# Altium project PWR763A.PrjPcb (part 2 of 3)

## Sheet PWR763A_3.SchDoc: PWR763A
size 431 x 279 mm; Date: Not shown in title block; ApprovedBy: Not shown in title block; CheckedBy: Not shown in title block; Author: Not shown in title block; CompanyName: Not shown in title block; Engineer: Not shown in title block; Organization: Not shown in title block; Address1: Not shown in title block; Address2: Not shown in title block; Address3: Not shown in title block; Address4: Not shown in title block; DocumentNumber: 1; Revision: Use project parameter SCH_Rev; SheetNumber: 3; SheetTotal: 6; PageSetup: Record=PageOptions¦CenterHorizontal=True¦CenterVertical=True¦PrintScale=1.00¦XCorrection=1.00¦YCorrection=1.00¦PrintKind=0¦BorderSize=5000000¦LeftOffset=0¦BottomOffset=0¦Orientation=2¦PaperLength=1000¦PaperWidth=1000¦Scale=100¦PaperSource=15¦PrintQuality=600¦MediaType=1¦DitherType=10¦PaperKind=Letter¦PrintScaleMode=1
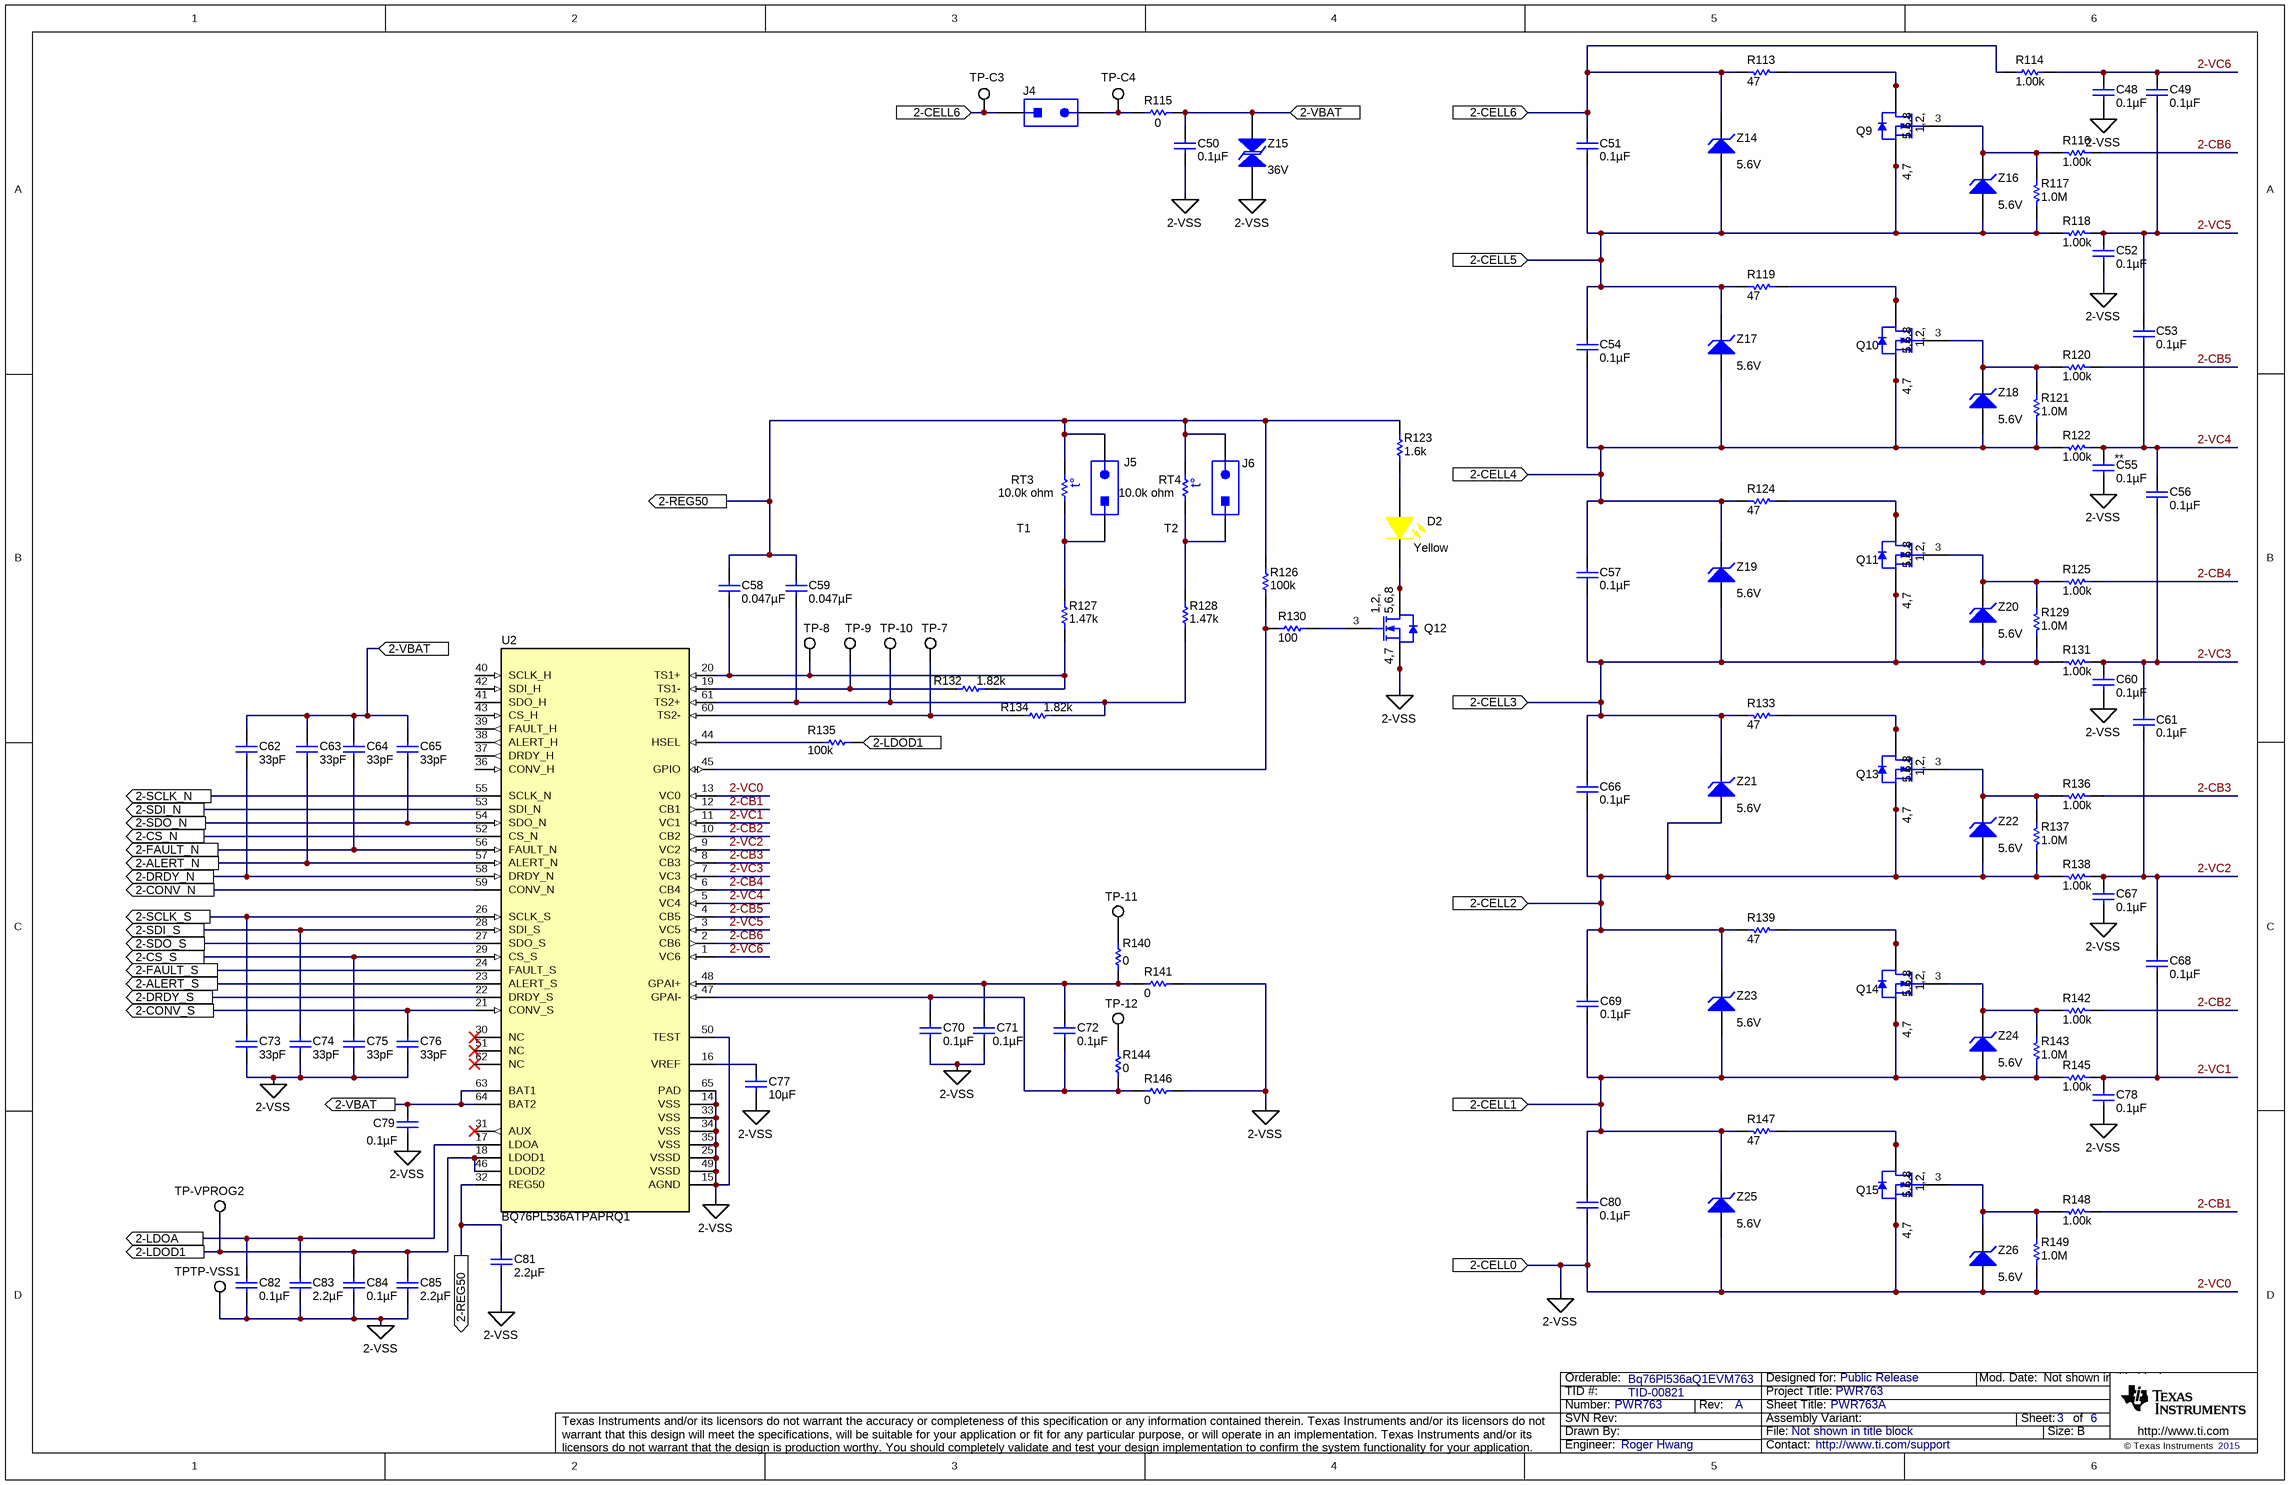
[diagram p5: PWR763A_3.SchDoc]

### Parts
C48  ValueDisplayed: 0.1µF  [0603]  (hidden comment: 06035C104KAT2A)
C49  ValueDisplayed: 0.1µF  [0603]  (hidden comment: GRM188R72A104KA35D)
C50  ValueDisplayed: 0.1µF  [0603]  (hidden comment: GRM188R72A104KA35D)
C51  ValueDisplayed: 0.1µF  [0603]  (hidden comment: 06035C104KAT2A)
C52  ValueDisplayed: 0.1µF  [0603]  (hidden comment: 06035C104KAT2A)
C53  ValueDisplayed: 0.1µF  [0603]  (hidden comment: GRM188R72A104KA35D)
C54  ValueDisplayed: 0.1µF  [0603]  (hidden comment: 06035C104KAT2A)
C55  ValueDisplayed: 0.1µF  [0603]  (hidden comment: 06035C104KAT2A)
C56  ValueDisplayed: 0.1µF  [0603]  (hidden comment: GRM188R72A104KA35D)
C57  ValueDisplayed: 0.1µF  [0603]  (hidden comment: 06035C104KAT2A)
C58  ValueDisplayed: 0.047µF  [0603]  (hidden comment: GRM188R71C473KA01D)
C59  ValueDisplayed: 0.047µF  [0603]  (hidden comment: GRM188R71C473KA01D)
C60  ValueDisplayed: 0.1µF  [0603]  (hidden comment: 06035C104KAT2A)
C61  ValueDisplayed: 0.1µF  [0603]  (hidden comment: GRM188R72A104KA35D)
C62  ValueDisplayed: 33pF  [0603]  (hidden comment: GRM1885C1H330JA01D)
C63  ValueDisplayed: 33pF  [0603]  (hidden comment: GRM1885C1H330JA01D)
C64  ValueDisplayed: 33pF  [0603]  (hidden comment: GRM1885C1H330JA01D)
C65  ValueDisplayed: 33pF  [0603]  (hidden comment: GRM1885C1H330JA01D)
C66  ValueDisplayed: 0.1µF  [0603]  (hidden comment: 06035C104KAT2A)
C67  ValueDisplayed: 0.1µF  [0603]  (hidden comment: 06035C104KAT2A)
C68  ValueDisplayed: 0.1µF  [0603]  (hidden comment: GRM188R72A104KA35D)
C69  ValueDisplayed: 0.1µF  [0603]  (hidden comment: GRM188R72A104KA35D)
C70  ValueDisplayed: 0.1µF  [0603]  (hidden comment: C0603C104K4RACTU)
C71  ValueDisplayed: 0.1µF  [0603]  (hidden comment: C0603C104K4RACTU)
C72  ValueDisplayed: 0.1µF  [0603]  (hidden comment: C0603C104K4RACTU)
C73  ValueDisplayed: 33pF  [0603]  (hidden comment: GRM1885C1H330JA01D)
C74  ValueDisplayed: 33pF  [0603]  (hidden comment: GRM1885C1H330JA01D)
C75  ValueDisplayed: 33pF  [0603]  (hidden comment: GRM1885C1H330JA01D)
C76  ValueDisplayed: 33pF  [0603]  (hidden comment: GRM1885C1H330JA01D)
C77  ValueDisplayed: 10µF  [0805_145]  (hidden comment: C2012X7R1A106M125AC)
C78  ValueDisplayed: 0.1µF  [0603]  (hidden comment: 06035C104KAT2A)
C79  ValueDisplayed: 0.1µF  [0603]  (hidden comment: 06035C104KAT2A)
C80  ValueDisplayed: 0.1µF  [0603]  (hidden comment: 06035C104KAT2A)
C81  ValueDisplayed: 2.2µF  [0805_HV]  (hidden comment: GRM21BR71A225KA01L)
C82  ValueDisplayed: 0.1µF  [0603]  (hidden comment: 06035C104KAT2A)
C83  ValueDisplayed: 2.2µF  [0805_HV]  (hidden comment: GRM21BR71A225KA01L)
C84  ValueDisplayed: 0.1µF  [0603]  (hidden comment: 06035C104KAT2A)
C85  ValueDisplayed: 2.2µF  [0805_HV]  (hidden comment: GRM21BR71A225KA01L)
D2  value Yellow  [APT1608_Yellow]  (hidden comment: APT1608SYCK)
J4  PEC02SAAN  [CONN_PEC02SAAN]  (value not drawn)
J5  PEC02SAAN  [CONN_PEC02SAAN]  (value not drawn)
J6  PEC02SAAN  [CONN_PEC02SAAN]  (value not drawn)
Q9  CSD16301Q2  [TRANS_NexFET_Q2]  (value not drawn)
Q10  CSD16301Q2  [TRANS_NexFET_Q2]  (value not drawn)
Q11  CSD16301Q2  [TRANS_NexFET_Q2]  (value not drawn)
Q12  CSD16301Q2  [TRANS_NexFET_Q2]  (value not drawn)
Q13  CSD16301Q2  [TRANS_NexFET_Q2]  (value not drawn)
Q14  CSD16301Q2  [TRANS_NexFET_Q2]  (value not drawn)
Q15  CSD16301Q2  [TRANS_NexFET_Q2]  (value not drawn)
R113  ValueDisplayed: 47  [2512]  (hidden comment: CRCW251247R0JNEG)
R114  ValueDisplayed: 1.00k  [0603]  (hidden comment: RG1608P-102-B-T5)
R115  ValueDisplayed: 0  [0805_HV]  (hidden comment: CRCW08050000Z0EA)
R116  ValueDisplayed: 1.00k  [0603]  (hidden comment: RG1608P-102-B-T5)
R117  ValueDisplayed: 1.0M  [0603]  (hidden comment: CRCW06031M00JNEA)
R118  ValueDisplayed: 1.00k  [0603]  (hidden comment: RG1608P-102-B-T5)
R119  ValueDisplayed: 47  [2512]  (hidden comment: CRCW251247R0JNEG)
R120  ValueDisplayed: 1.00k  [0603]  (hidden comment: RG1608P-102-B-T5)
R121  ValueDisplayed: 1.0M  [0603]  (hidden comment: CRCW06031M00JNEA)
R122  ValueDisplayed: 1.00k  [0603]  (hidden comment: RG1608P-102-B-T5)
R123  ValueDisplayed: 1.6k  [0603]  (hidden comment: CRCW06031K60JNEA)
R124  ValueDisplayed: 47  [2512]  (hidden comment: CRCW251247R0JNEG)
R125  ValueDisplayed: 1.00k  [0603]  (hidden comment: RG1608P-102-B-T5)
R126  ValueDisplayed: 100k  [0603]  (hidden comment: CRCW0603100KFKEA)
R127  ValueDisplayed: 1.47k  [0603]  (hidden comment: CRCW06031K47FKEA)
R128  ValueDisplayed: 1.47k  [0603]  (hidden comment: CRCW06031K47FKEA)
R129  ValueDisplayed: 1.0M  [0603]  (hidden comment: CRCW06031M00JNEA)
R130  ValueDisplayed: 100  [0603]  (hidden comment: CRCW0603100RJNEA)
R131  ValueDisplayed: 1.00k  [0603]  (hidden comment: RG1608P-102-B-T5)
R132  ValueDisplayed: 1.82k  [0603]  (hidden comment: CRCW06031K82FKEA)
R133  ValueDisplayed: 47  [2512]  (hidden comment: CRCW251247R0JNEG)
R134  ValueDisplayed: 1.82k  [0603]  (hidden comment: CRCW06031K82FKEA)
R135  ValueDisplayed: 100k  [0603]  (hidden comment: CRCW0603100KFKEA)
R136  ValueDisplayed: 1.00k  [0603]  (hidden comment: RG1608P-102-B-T5)
R137  ValueDisplayed: 1.0M  [0603]  (hidden comment: CRCW06031M00JNEA)
R138  ValueDisplayed: 1.00k  [0603]  (hidden comment: RG1608P-102-B-T5)
R139  ValueDisplayed: 47  [2512]  (hidden comment: CRCW251247R0JNEG)
R140  ValueDisplayed: 0  [0603]  (hidden comment: CRCW06030000Z0EA)
R141  ValueDisplayed: 0  [0603]  (hidden comment: CRCW06030000Z0EA)
R142  ValueDisplayed: 1.00k  [0603]  (hidden comment: RG1608P-102-B-T5)
R143  ValueDisplayed: 1.0M  [0603]  (hidden comment: CRCW06031M00JNEA)
R144  ValueDisplayed: 0  [0603]  (hidden comment: CRCW06030000Z0EA)
R145  ValueDisplayed: 1.00k  [0603]  (hidden comment: RG1608P-102-B-T5)
R146  ValueDisplayed: 0  [0603]  (hidden comment: CRCW06030000Z0EA)
R147  ValueDisplayed: 47  [2512]  (hidden comment: CRCW251247R0JNEG)
R148  ValueDisplayed: 1.00k  [0603]  (hidden comment: RG1608P-102-B-T5)
R149  ValueDisplayed: 1.0M  [0603]  (hidden comment: CRCW06031M00JNEA)
RT3  value 10.0k ohm  [0603]  (hidden comment: ERT-J1VG103FA)
RT4  value 10.0k ohm  [0603]  (hidden comment: ERT-J1VG103FA)
TP-7  5015  [Testpoint_Keystone_Miniature]  (value not drawn)
TP-8  5015  [Testpoint_Keystone_Miniature]  (value not drawn)
TP-9  5015  [Testpoint_Keystone_Miniature]  (value not drawn)
TP-10  5015  [Testpoint_Keystone_Miniature]  (value not drawn)
TP-11  5015  [Testpoint_Keystone_Miniature]  (value not drawn)
TP-12  5015  [Testpoint_Keystone_Miniature]  (value not drawn)
TP-C3  5015  [Testpoint_Keystone_Miniature]  (value not drawn)
TP-C4  5015  [Testpoint_Keystone_Miniature]  (value not drawn)
TP-VPROG2  5015  [Testpoint_Keystone_Miniature]  (value not drawn)
TPTP-VSS1  5015  [Testpoint_Keystone_Miniature]  (value not drawn)
U2  BQ76PL536ATPAPRQ1  [PAP0064F_N]
Z14  value 5.6V  [SOD-123]  (hidden comment: MMSZ5232B-7-F)
Z15  value 36V  [SMA]  (hidden comment: SMAJ36CA)
Z16  value 5.6V  [SOD-123]  (hidden comment: MMSZ5232B-7-F)
Z17  value 5.6V  [SOD-123]  (hidden comment: MMSZ5232B-7-F)
Z18  value 5.6V  [SOD-123]  (hidden comment: MMSZ5232B-7-F)
Z19  value 5.6V  [SOD-123]  (hidden comment: MMSZ5232B-7-F)
Z20  value 5.6V  [SOD-123]  (hidden comment: MMSZ5232B-7-F)
Z21  value 5.6V  [SOD-123]  (hidden comment: MMSZ5232B-7-F)
Z22  value 5.6V  [SOD-123]  (hidden comment: MMSZ5232B-7-F)
Z23  value 5.6V  [SOD-123]  (hidden comment: MMSZ5232B-7-F)
Z24  value 5.6V  [SOD-123]  (hidden comment: MMSZ5232B-7-F)
Z25  value 5.6V  [SOD-123]  (hidden comment: MMSZ5232B-7-F)
Z26  value 5.6V  [SOD-123]  (hidden comment: MMSZ5232B-7-F)

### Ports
2-ALERT_N, 2-ALERT_S, 2-CELL0, 2-CELL1, 2-CELL2, 2-CELL3, 2-CELL4, 2-CELL5, 2-CELL6, 2-CONV_N, 2-CONV_S, 2-CS_N, 2-CS_S, 2-DRDY_N, 2-DRDY_S, 2-FAULT_N, 2-FAULT_S, 2-LDOA, 2-LDOD1, 2-REG50, 2-SCLK_N, 2-SCLK_S, 2-SDI_N, 2-SDI_S, 2-SDO_N, 2-SDO_S, 2-VBAT

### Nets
2-VC0: C48.2 C50.2 C52.2 C55.2 C60.2 C67.2 C70.2 C71.2 C73.2 C74.2 C75.2 C76.2 C77.2 C78.2 C79.2 C80.2 C81.2 C82.2 C83.2 C84.2 C85.2 Q12.4(S) Q12.7(S) Q15.4(S) Q15.7(S) R141.2 R146.2 R149.1 TPTP-VSS1.1 U2.13(VC0) U2.14(VSS) U2.15(AGND) U2.25(VSSD) U2.33(VSS) U2.34(VSS) U2.35(VSS) U2.49(VSSD) U2.50(TEST) U2.65(PAD) Z15.1 Z25.2(A) Z26.2(A) ; port 2-CELL0  [also labelled 2-VSS]
2-ALERT_N: C63.2 U2.57(ALERT_N) ; port 2-ALERT_N
2-ALERT_S: U2.23(ALERT_S) ; port 2-ALERT_S
2-CB1: R148.1 U2.12(CB1)
2-CB2: R142.1 U2.10(CB2)
2-CB3: R136.1 U2.8(CB3)
2-CB4: R125.1 U2.6(CB4)
2-CB5: R120.1 U2.4(CB5)
2-CB6: R116.1 U2.2(CB6)
2-CELL1: C69.2 C80.1 Q14.4(S) Q14.7(S) R143.1 R145.2 R147.2 Z23.2(A) Z24.2(A) Z25.1(K) ; port 2-CELL1
2-CELL2: C66.2 C69.1 Q13.4(S) Q13.7(S) R137.1 R138.2 R139.2 Z21.2(A) Z22.2(A) Z23.1(K) ; port 2-CELL2
2-CELL3: C57.2 C66.1 Q11.4(S) Q11.7(S) R129.1 R131.2 R133.2 Z19.2(A) Z20.2(A) Z21.1(K) ; port 2-CELL3
2-CELL4: C54.2 C57.1 Q10.4(S) Q10.7(S) R121.1 R122.2 R124.2 Z17.2(A) Z18.2(A) Z19.1(K) ; port 2-CELL4
2-CELL5: C51.2 C54.1 Q9.4(S) Q9.7(S) R117.1 R118.2 R119.2 Z14.2(A) Z16.2(A) Z17.1(K) ; port 2-CELL5
2-CELL6: C51.1 J4.1 R113.2 R114.2 TP-C3.1 Z14.1(K) ; port 2-CELL6
2-CONV_N: U2.59(CONV_N) ; port 2-CONV_N
2-CONV_S: C76.1 U2.21(CONV_S) ; port 2-CONV_S
2-CS_N: U2.52(CS_N) ; port 2-CS_N
2-CS_S: C75.1 U2.29(CS_S) ; port 2-CS_S
2-DRDY_N: C62.2 U2.58(DRDY_N) ; port 2-DRDY_N
2-DRDY_S: U2.22(DRDY_S) ; port 2-DRDY_S
2-FAULT_N: C64.2 U2.56(FAULT_N) ; port 2-FAULT_N
2-FAULT_S: U2.24(FAULT_S) ; port 2-FAULT_S
2-LDOA: C82.1 C83.1 U2.17(LDOA) ; port 2-LDOA
2-LDOD1: C84.1 C85.1 R135.2 TP-VPROG2.1 U2.18(LDOD1) U2.46(LDOD2) ; port 2-LDOD1
2-REG50: C58.1 C59.1 C81.1 J5.2 J6.2 R123.2 R126.2 RT3.2 RT4.2 U2.32(REG50) ; port 2-REG50
2-SCLK_N: U2.55(SCLK_N) ; port 2-SCLK_N
2-SCLK_S: C73.1 U2.26(SCLK_S) ; port 2-SCLK_S
2-SDI_N: U2.53(SDI_N) ; port 2-SDI_N
2-SDI_S: C74.1 U2.28(SDI_S) ; port 2-SDI_S
2-SDO_N: C65.2 U2.54(SDO_N) ; port 2-SDO_N
2-SDO_S: U2.27(SDO_S) ; port 2-SDO_S
2-VBAT: C50.1 C62.1 C63.1 C64.1 C65.1 C79.1 R115.2 U2.63(BAT1) U2.64(BAT2) Z15.2 ; port 2-VBAT
2-VC1: C68.2 C78.1 R145.1 U2.11(VC1)
2-VC2: C61.2 C67.1 C68.1 R138.1 U2.9(VC2)
2-VC3: C56.2 C60.1 C61.1 R131.1 U2.7(VC3)
2-VC4: C53.2 C55.1 C56.1 R122.1 U2.5(VC4)
2-VC5: C49.2 C52.1 C53.1 R118.1 U2.3(VC5)
2-VC6: C48.1 C49.1 R114.1 U2.1(VC6)
NetC58_2: C58.2 R127.1 R132.2 TP-8.1 U2.20(TS1+)
NetC59_2: C59.2 R128.1 R134.2 TP-10.1 U2.61(TS2+)
NetC70_1: C70.1 C72.2 R144.1 R146.1 U2.47(GPAI-)
NetC71_1: C71.1 C72.1 R140.1 R141.1 U2.48(GPAI+)
NetC77_1: C77.1 U2.16(VREF)
NetD2_1: D2.1(A) R123.1
NetD2_2: D2.2(K) Q12.1(D) Q12.2(D) Q12.5(D) Q12.6(D) Q12.8(D)
NetJ4_2: J4.2 R115.1 TP-C4.1
NetJ5_1: J5.1 R127.2 RT3.1
NetJ6_1: J6.1 R128.2 RT4.1
NetQ9_1: Q9.1(D) Q9.2(D) Q9.5(D) Q9.6(D) Q9.8(D) R113.1
NetQ9_3: Q9.3(G) R116.2 R117.2 Z16.1(K)
NetQ10_1: Q10.1(D) Q10.2(D) Q10.5(D) Q10.6(D) Q10.8(D) R119.1
NetQ10_3: Q10.3(G) R120.2 R121.2 Z18.1(K)
NetQ11_1: Q11.1(D) Q11.2(D) Q11.5(D) Q11.6(D) Q11.8(D) R124.1
NetQ11_3: Q11.3(G) R125.2 R129.2 Z20.1(K)
NetQ12_3: Q12.3(G) R130.2
NetQ13_1: Q13.1(D) Q13.2(D) Q13.5(D) Q13.6(D) Q13.8(D) R133.1
NetQ13_3: Q13.3(G) R136.2 R137.2 Z22.1(K)
NetQ14_1: Q14.1(D) Q14.2(D) Q14.5(D) Q14.6(D) Q14.8(D) R139.1
NetQ14_3: Q14.3(G) R142.2 R143.2 Z24.1(K)
NetQ15_1: Q15.1(D) Q15.2(D) Q15.5(D) Q15.6(D) Q15.8(D) R147.1
NetQ15_3: Q15.3(G) R148.2 R149.2 Z26.1(K)
NetR126_1: R126.1 R130.1 U2.45(GPIO)
NetR132_1: R132.1 TP-9.1 U2.19(TS1-)
NetR134_1: R134.1 TP-7.1 U2.60(TS2-)
NetR135_1: R135.1 U2.44(HSEL)
NetR140_2: R140.2 TP-11.1
NetR144_2: R144.2 TP-12.1

Not connected (* = marked no-connect by the designer): U2 30(NC)* 31(AUX)* 36(CONV_H) 37(DRDY_H) 38(ALERT_H) 39(FAULT_H) 40(SCLK_H) 41(SDO_H) 42(SDI_H) 43(CS_H) 51(NC)* 62(NC)*

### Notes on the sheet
- (near C55) **
- (near RT3) T1
- (near RT4) T2

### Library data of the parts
C48 C51 C52 C54 C55 C57 C60 C66 C67 C78-C80 C82 C84 = 06035C104KAT2A: CAP, CERM, 0.1 µF, 50 V, +/- 10%, X7R, 0603; Manufacturer: AVX; Polarized: N; CompType: Capacitor; Value: 0.1uF; U/M: EA; Cap_F: 0.0000001; Tolerance_%: 10; Value1: Unknown; VDC_V: 50; Value2: 50V; TaMin_C: -55; TaMax_C: 125
C49 C50 C53 C56 C61 C68 C69 = GRM188R72A104KA35D: CAP, CERM, 0.1 µF, 100 V, +/- 10%, X7R, 0603; Manufacturer: MuRata; Polarized: N; CompType: Capacitor; Value: 0.1uF; U/M: EA; Cap_F: 0.0000001; Tolerance_%: 10; Value1: Unknown; VDC_V: 100; Value2: 100V; TaMin_C: -55; TaMax_C: 125
C58 C59 = GRM188R71C473KA01D: CAP, CERM, 0.047 µF, 16 V, +/- 10%, X7R, 0603; Manufacturer: MuRata; Polarized: N; CompType: Capacitor; Value: 0.047uF; U/M: EA; Cap_F: 0.000000047; Tolerance_%: 10; Value1: Unknown; VDC_V: 16; Value2: 16V; TaMin_C: -55; TaMax_C: 125
C62-C65 C73-C76 = GRM1885C1H330JA01D: CAP, CERM, 33 pF, 50 V, +/- 5%, C0G/NP0, 0603; Manufacturer: MuRata; Polarized: N; CompType: Capacitor; Value: 33pF; U/M: EA; Cap_F: 0.000000000033; Tolerance_%: 5; Value1: Unknown; VDC_V: 50; Value2: 50V; TaMin_C: -55; TaMax_C: 125
C70-C72 = C0603C104K4RACTU: CAP, CERM, 0.1 µF, 16 V, +/- 10%, X7R, 0603; Manufacturer: Kemet; Polarized: N; CompType: Capacitor; Value: 0.1uF; U/M: EA; Cap_F: 0.0000001; Tolerance_%: 10; Value1: Unknown; VDC_V: 16; Value2: 16V; TaMin_C: -55; TaMax_C: 125
C77 = C2012X7R1A106M125AC: CAP, CERM, 10 µF, 10 V, +/- 20%, X7R, 0805; Manufacturer: TDK; Polarized: N; CompType: Capacitor; Value: 10uF; U/M: EA; Cap_F: 0.00001; Tolerance_%: 20; Value1: Unknown; VDC_V: 10; Value2: 10V; TaMin_C: -55; TaMax_C: 125; Cap_Case: 0805
C81 C83 C85 = GRM21BR71A225KA01L: CAP, CERM, 2.2 µF, 10 V, +/- 10%, X7R, 0805; Manufacturer: MuRata; Polarized: N; CompType: Capacitor; Value: 2.2uF; U/M: EA; Cap_F: 0.0000022; Tolerance_%: 10; ESR_ohm: 0.006; Value1: 0.006 ohm; Value2: 10V; TaMin_C: -55; TaMax_C: 125; Cap_Case: 0805
D2 = APT1608SYCK: LED, Yellow, SMD; Manufacturer: Kingbright; SymbolCreator: Altium; Vf_V: 2.5; Value2: 2.5V; Io_A: 0.02; Vr_V: 5; Ir_A: 1e-005; Tjmax_C: 85; Value1: W; Angle: 120; U/M: EA
J4-J6 = PEC02SAAN: Header, 100mil, 2x1, Tin, TH; Manufacturer: Sullins Connector Solutions; SymbolCreator: a0412235; U/M: EA
Q9-Q15 = CSD16301Q2: MOSFET, N-CH, 25 V, 5 A, SON 2x2mm; Manufacturer: Texas Instruments; Alternate Manufacturer: None; U/M: EA; ChType: N; Value: 25V; VdsMax_V: 25; Value1: 0.023 ohm; Rdson45_ohm: 0.023; Value2: 2 nC; QgTyp_nC: 2; Vgs_V: 10; IdsMax_A: 5
R113 R119 R124 R133 R139 R147 = CRCW251247R0JNEG: RES, 47, 5%, 1 W, 2512; Manufacturer: Vishay-Dale; CompType: Resistor; Value: 47; Value_Code: 47R0; Tolerance_%: 5; Power_W: 1; Value2: 1W; VDC_V: 500; TempCo: 200 ppm/C; EIA_Code: E24; U/M: EA
R114 R116 R118 R120 R122 R125 R131 R136 R138 R142 R145 R148 = RG1608P-102-B-T5: RES, 1.00 k, 0.1%, 0.1 W, 0603; Manufacturer: Susumu Co Ltd; CompType: Resistor; Value: 1.00k; Res_ohm: 1000; Value_Code: 1k00; Tolerance_%: 0.1; Value2: 0.1W; VDC_V: 75; TempCo: 25 ppm/C; EIA_Code: E192; U/M: EA
R115 = CRCW08050000Z0EA: RES, 0, 5%, 0.125 W, 0805; Manufacturer: Vishay-Dale; CompType: Resistor; Value: 0; Value_Code: 0000; Tolerance_%: 5; Power_W: 0.125; Value2: 0.125W; VDC_V: 150; TempCo: 200 ppm/C; EIA_Code: E24; U/M: EA
R117 R121 R129 R137 R143 R149 = CRCW06031M00JNEA: RES, 1.0 M, 5%, 0.1 W, 0603; Manufacturer: Vishay-Dale; CompType: Resistor; Value: 1.0Meg; Res_ohm: 1000000; Value_Code: 1M00; Tolerance_%: 5; Power_W: 0.1; Value2: 0.1W; VDC_V: 75; TempCo: 200 ppm/C; EIA_Code: E24; U/M: EA
R123 = CRCW06031K60JNEA: RES, 1.6 k, 5%, 0.1 W, 0603; Manufacturer: Vishay-Dale; CompType: Resistor; Value: 1.6k; Res_ohm: 1600; Value_Code: 1k60; Tolerance_%: 5; Power_W: 0.1; Value2: 0.1W; VDC_V: 75; TempCo: 200 ppm/C; EIA_Code: E24; U/M: EA
R126 R135 = CRCW0603100KFKEA: RES, 100 k, 1%, 0.1 W, 0603; Manufacturer: Vishay-Dale; CompType: Resistor; Value: 100k; Res_ohm: 100000; Tolerance_%: 1; Power_W: 0.1; Value2: 0.1W; VDC_V: 75; TempCo: 100 ppm/C; EIA_Code: E96; U/M: EA
R127 R128 = CRCW06031K47FKEA: RES, 1.47 k, 1%, 0.1 W, 0603; Manufacturer: Vishay-Dale; CompType: Resistor; Value: 1.47k; Res_ohm: 1470; Value_Code: 1k47; Tolerance_%: 1; Power_W: 0.1; Value2: 0.1W; VDC_V: 75; TempCo: 100 ppm/C; EIA_Code: E96; U/M: EA
R130 = CRCW0603100RJNEA: RES, 100, 5%, 0.1 W, 0603; Manufacturer: Vishay-Dale; CompType: Resistor; Value: 100; Value_Code: 100R; Tolerance_%: 5; Power_W: 0.1; Value2: 0.1W; VDC_V: 75; TempCo: 200 ppm/C; EIA_Code: E24; U/M: EA
R132 R134 = CRCW06031K82FKEA: RES, 1.82 k, 1%, 0.1 W, 0603; Manufacturer: Vishay-Dale; CompType: Resistor; Value: 1.82k; Res_ohm: 1820; Value_Code: 1k82; Tolerance_%: 1; Power_W: 0.1; Value2: 0.1W; VDC_V: 75; TempCo: 100 ppm/C; EIA_Code: E96; U/M: EA
R140 R141 R144 R146 = CRCW06030000Z0EA: RES, 0, 5%, 0.1 W, 0603; Manufacturer: Vishay-Dale; CompType: Resistor; Value: 0; Value_Code: 0000; Tolerance_%: 5; Power_W: 0.1; Value2: 0.1W; VDC_V: 75; TempCo: 200 ppm/C; EIA_Code: E24; U/M: EA
RT3 RT4 = ERT-J1VG103FA: Thermistor NTC, 10.0k ohm, 1%, 0603; Manufacturer: Panasonic; Tolerance_%: 1; Power_W: 0.1; TaMin_C: -40; TaMax_C: 125; U/M: EA
TP-7-TP-12 TP-C3 TP-C4 TP-VPROG2 TPTP-VSS1 = 5015: Test Point, Miniature, SMT; Manufacturer: Keystone; CompType: Test Point Loop; U/M: EA
U2 = BQ76PL536ATPAPRQ1: 3 to 6 Series Cell Lithium-Ion Battery Monitor and Secondary Protection IC for EV and HEV Application, PAP0064F; Alternate PartNumber: BQ76PL536ATPAPTQ1; Manufacturer: Texas Instruments; SymbolCreator: Altium; U/M: EA
Z14 Z16-Z26 = MMSZ5232B-7-F: Diode, Zener, 5.6 V, 500 mW, SOD-123; Manufacturer: Diodes Inc.; SymbolCreator: a0412235; U/M: EA; Power_W: 0.5; Vz_V: 5.6; Value1: 0.5W; RJA_CperW: 350; AEC Category: Q101
Z15 = SMAJ36CA: Diode, TVS, Bi, 36 V, 400 W, SMA; Manufacturer: Littelfuse; U/M: EA; Power_W: 400; Vr_V: 36; Value1: 400W; RJA_CperW: 120

## Sheet PWR763A_4.SchDoc: PWR763A
size 431 x 279 mm; Date: Not shown in title block; ApprovedBy: Not shown in title block; CheckedBy: Not shown in title block; Author: Not shown in title block; CompanyName: Not shown in title block; Engineer: Not shown in title block; Organization: Not shown in title block; Address1: Not shown in title block; Address2: Not shown in title block; Address3: Not shown in title block; Address4: Not shown in title block; DocumentNumber: 1; Revision: Use project parameter SCH_Rev; SheetNumber: 4; SheetTotal: 6; PageSetup: Record=PageOptions¦CenterHorizontal=True¦CenterVertical=True¦PrintScale=1.00¦XCorrection=1.00¦YCorrection=1.00¦PrintKind=0¦BorderSize=5000000¦LeftOffset=0¦BottomOffset=0¦Orientation=2¦PaperLength=1000¦PaperWidth=1000¦Scale=100¦PaperSource=15¦PrintQuality=600¦MediaType=1¦DitherType=10¦PaperKind=Letter¦PrintScaleMode=1
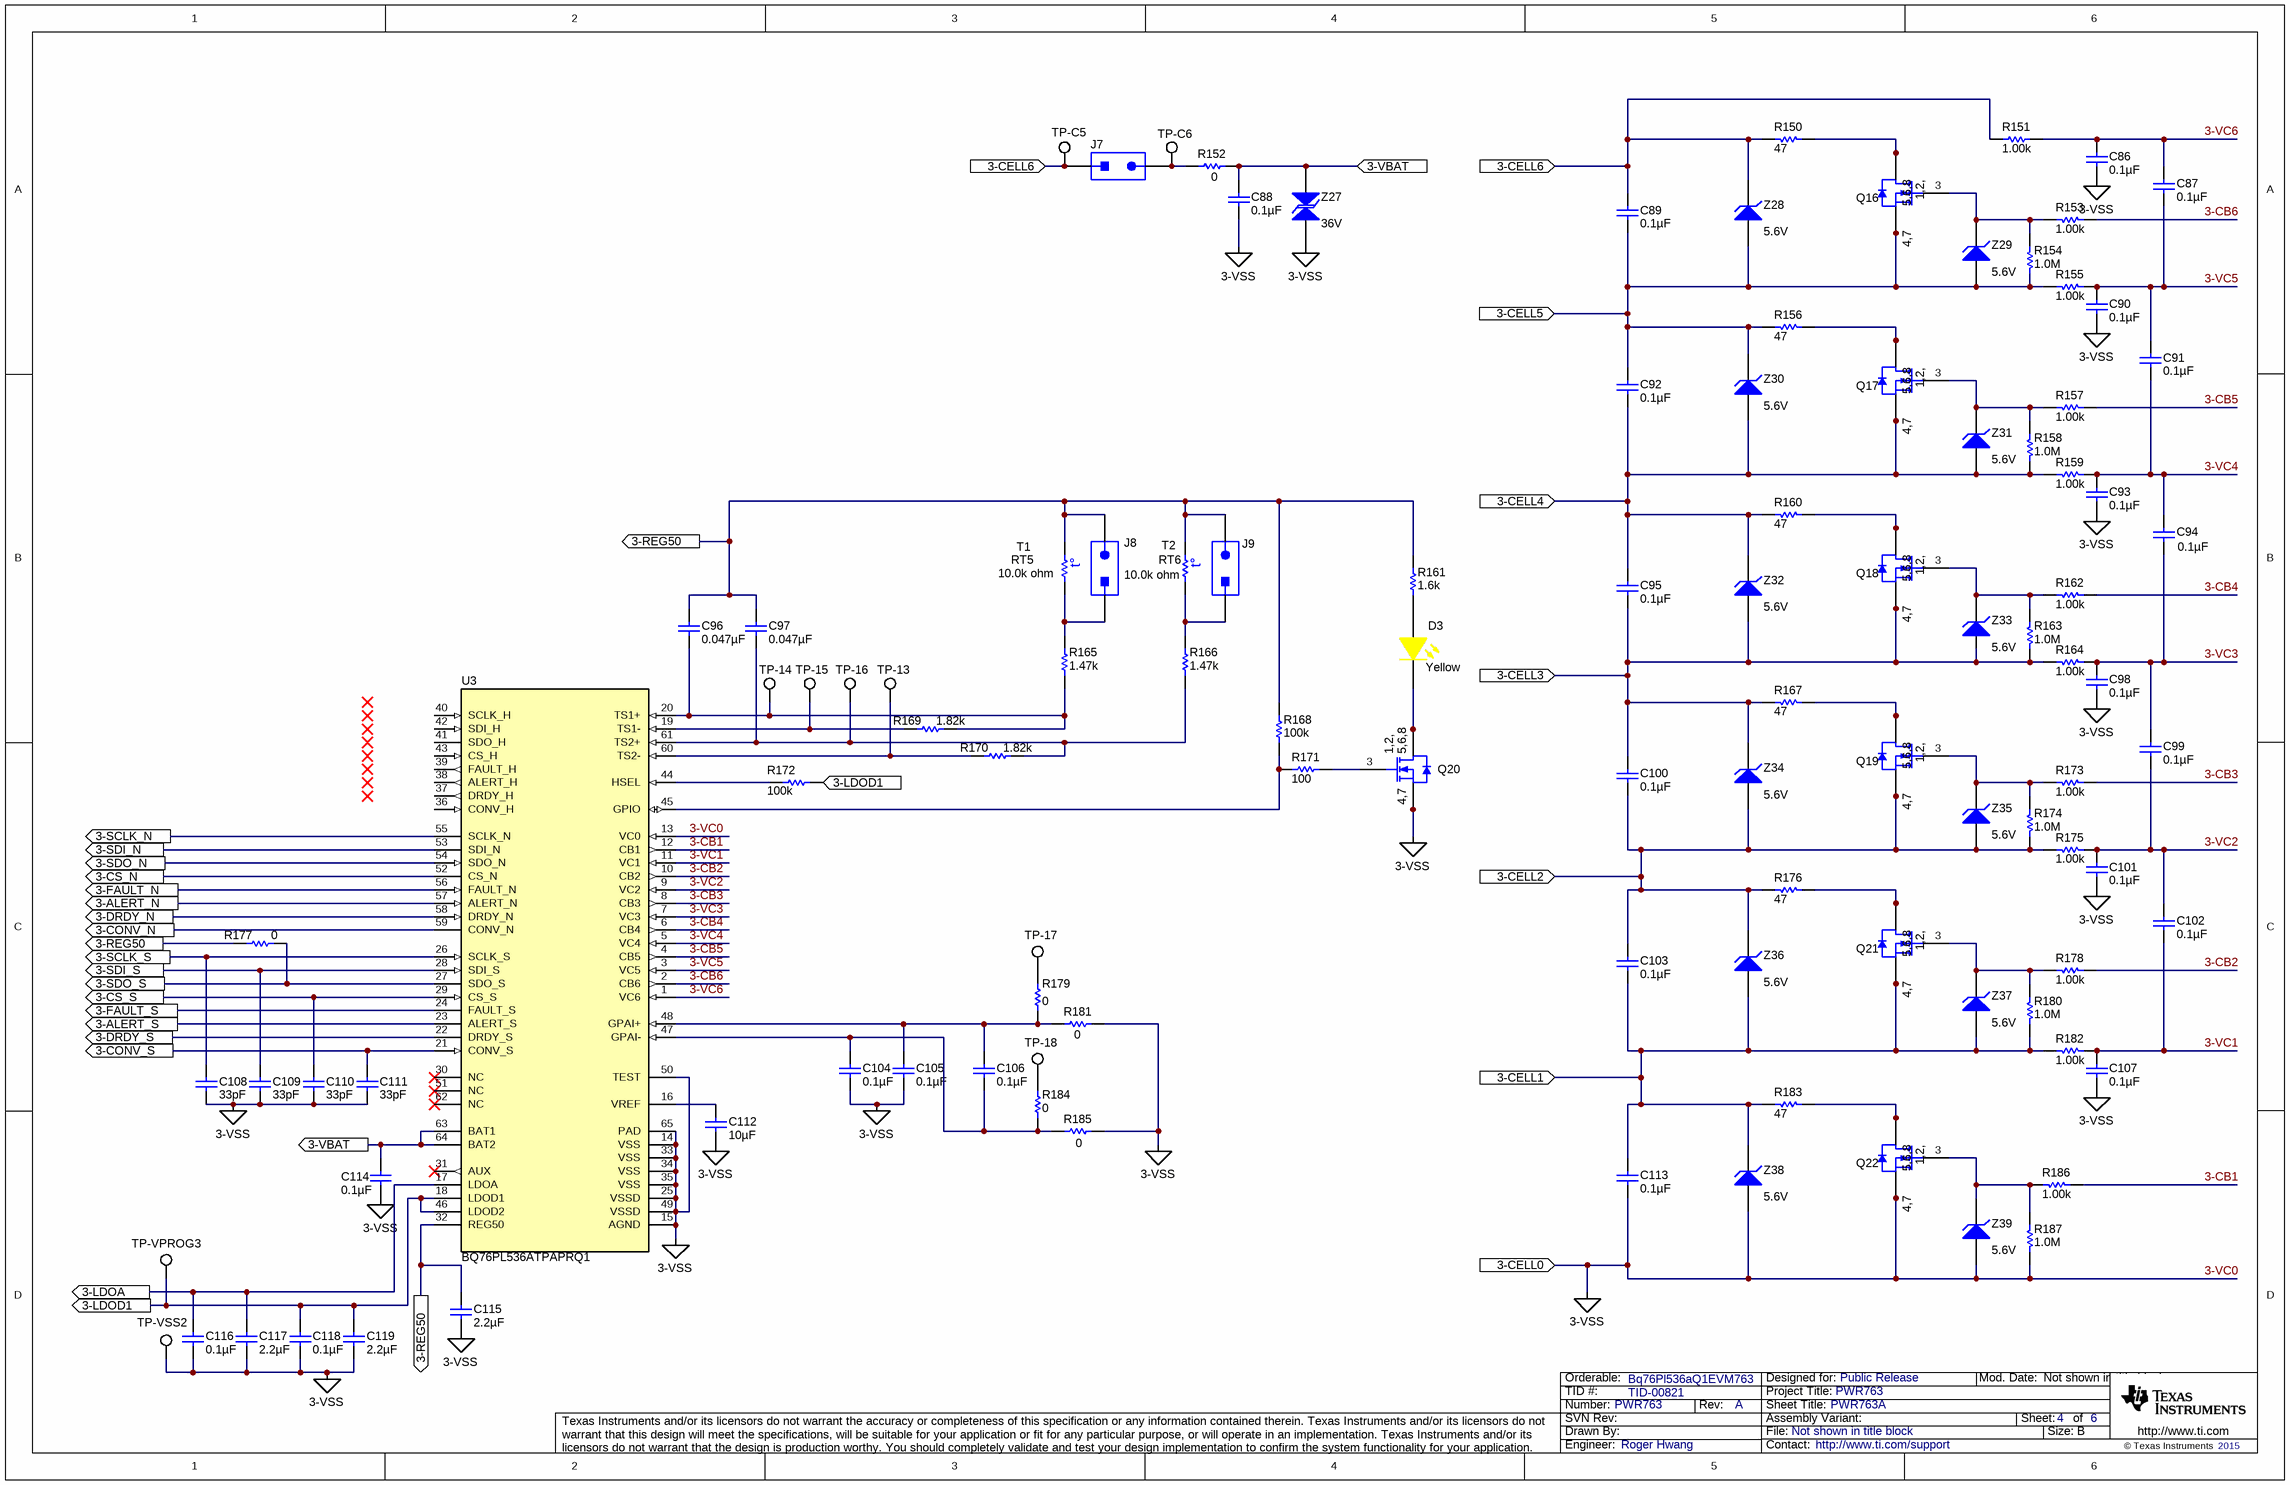
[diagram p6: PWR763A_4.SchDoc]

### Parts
C86  ValueDisplayed: 0.1µF  [0603]  (hidden comment: 06035C104KAT2A)
C87  ValueDisplayed: 0.1µF  [0603]  (hidden comment: GRM188R72A104KA35D)
C88  ValueDisplayed: 0.1µF  [0603]  (hidden comment: GRM188R72A104KA35D)
C89  ValueDisplayed: 0.1µF  [0603]  (hidden comment: 06035C104KAT2A)
C90  ValueDisplayed: 0.1µF  [0603]  (hidden comment: 06035C104KAT2A)
C91  ValueDisplayed: 0.1µF  [0603]  (hidden comment: GRM188R72A104KA35D)
C92  ValueDisplayed: 0.1µF  [0603]  (hidden comment: 06035C104KAT2A)
C93  ValueDisplayed: 0.1µF  [0603]  (hidden comment: 06035C104KAT2A)
C94  ValueDisplayed: 0.1µF  [0603]  (hidden comment: GRM188R72A104KA35D)
C95  ValueDisplayed: 0.1µF  [0603]  (hidden comment: 06035C104KAT2A)
C96  ValueDisplayed: 0.047µF  [0603]  (hidden comment: GRM188R71C473KA01D)
C97  ValueDisplayed: 0.047µF  [0603]  (hidden comment: GRM188R71C473KA01D)
C98  ValueDisplayed: 0.1µF  [0603]  (hidden comment: 06035C104KAT2A)
C99  ValueDisplayed: 0.1µF  [0603]  (hidden comment: GRM188R72A104KA35D)
C100  ValueDisplayed: 0.1µF  [0603]  (hidden comment: 06035C104KAT2A)
C101  ValueDisplayed: 0.1µF  [0603]  (hidden comment: 06035C104KAT2A)
C102  ValueDisplayed: 0.1µF  [0603]  (hidden comment: GRM188R72A104KA35D)
C103  ValueDisplayed: 0.1µF  [0603]  (hidden comment: GRM188R72A104KA35D)
C104  ValueDisplayed: 0.1µF  [0603]  (hidden comment: C0603C104K4RACTU)
C105  ValueDisplayed: 0.1µF  [0603]  (hidden comment: C0603C104K4RACTU)
C106  ValueDisplayed: 0.1µF  [0603]  (hidden comment: C0603C104K4RACTU)
C107  ValueDisplayed: 0.1µF  [0603]  (hidden comment: 06035C104KAT2A)
C108  ValueDisplayed: 33pF  [0603]  (hidden comment: GRM1885C1H330JA01D)
C109  ValueDisplayed: 33pF  [0603]  (hidden comment: GRM1885C1H330JA01D)
C110  ValueDisplayed: 33pF  [0603]  (hidden comment: GRM1885C1H330JA01D)
C111  ValueDisplayed: 33pF  [0603]  (hidden comment: GRM1885C1H330JA01D)
C112  ValueDisplayed: 10µF  [0805_145]  (hidden comment: C2012X7R1A106M125AC)
C113  ValueDisplayed: 0.1µF  [0603]  (hidden comment: 06035C104KAT2A)
C114  ValueDisplayed: 0.1µF  [0603]  (hidden comment: 06035C104KAT2A)
C115  ValueDisplayed: 2.2µF  [0805_HV]  (hidden comment: GRM21BR71A225KA01L)
C116  ValueDisplayed: 0.1µF  [0603]  (hidden comment: 06035C104KAT2A)
C117  ValueDisplayed: 2.2µF  [0805_HV]  (hidden comment: GRM21BR71A225KA01L)
C118  ValueDisplayed: 0.1µF  [0603]  (hidden comment: 06035C104KAT2A)
C119  ValueDisplayed: 2.2µF  [0805_HV]  (hidden comment: GRM21BR71A225KA01L)
D3  value Yellow  [APT1608_Yellow]  (hidden comment: APT1608SYCK)
J7  PEC02SAAN  [CONN_PEC02SAAN]  (value not drawn)
J8  PEC02SAAN  [CONN_PEC02SAAN]  (value not drawn)
J9  PEC02SAAN  [CONN_PEC02SAAN]  (value not drawn)
Q16  CSD16301Q2  [TRANS_NexFET_Q2]  (value not drawn)
Q17  CSD16301Q2  [TRANS_NexFET_Q2]  (value not drawn)
Q18  CSD16301Q2  [TRANS_NexFET_Q2]  (value not drawn)
Q19  CSD16301Q2  [TRANS_NexFET_Q2]  (value not drawn)
Q20  CSD16301Q2  [TRANS_NexFET_Q2]  (value not drawn)
Q21  CSD16301Q2  [TRANS_NexFET_Q2]  (value not drawn)
Q22  CSD16301Q2  [TRANS_NexFET_Q2]  (value not drawn)
R150  ValueDisplayed: 47  [2512]  (hidden comment: CRCW251247R0JNEG)
R151  ValueDisplayed: 1.00k  [0603]  (hidden comment: RG1608P-102-B-T5)
R152  ValueDisplayed: 0  [0805_HV]  (hidden comment: CRCW08050000Z0EA)
R153  ValueDisplayed: 1.00k  [0603]  (hidden comment: RG1608P-102-B-T5)
R154  ValueDisplayed: 1.0M  [0603]  (hidden comment: CRCW06031M00JNEA)
R155  ValueDisplayed: 1.00k  [0603]  (hidden comment: RG1608P-102-B-T5)
R156  ValueDisplayed: 47  [2512]  (hidden comment: CRCW251247R0JNEG)
R157  ValueDisplayed: 1.00k  [0603]  (hidden comment: RG1608P-102-B-T5)
R158  ValueDisplayed: 1.0M  [0603]  (hidden comment: CRCW06031M00JNEA)
R159  ValueDisplayed: 1.00k  [0603]  (hidden comment: RG1608P-102-B-T5)
R160  ValueDisplayed: 47  [2512]  (hidden comment: CRCW251247R0JNEG)
R161  ValueDisplayed: 1.6k  [0603]  (hidden comment: CRCW06031K60JNEA)
R162  ValueDisplayed: 1.00k  [0603]  (hidden comment: RG1608P-102-B-T5)
R163  ValueDisplayed: 1.0M  [0603]  (hidden comment: CRCW06031M00JNEA)
R164  ValueDisplayed: 1.00k  [0603]  (hidden comment: RG1608P-102-B-T5)
R165  ValueDisplayed: 1.47k  [0603]  (hidden comment: CRCW06031K47FKEA)
R166  ValueDisplayed: 1.47k  [0603]  (hidden comment: CRCW06031K47FKEA)
R167  ValueDisplayed: 47  [2512]  (hidden comment: CRCW251247R0JNEG)
R168  ValueDisplayed: 100k  [0603]  (hidden comment: CRCW0603100KFKEA)
R169  ValueDisplayed: 1.82k  [0603]  (hidden comment: CRCW06031K82FKEA)
R170  ValueDisplayed: 1.82k  [0603]  (hidden comment: CRCW06031K82FKEA)
R171  ValueDisplayed: 100  [0603]  (hidden comment: CRCW0603100RJNEA)
R172  ValueDisplayed: 100k  [0603]  (hidden comment: CRCW0603100KFKEA)
R173  ValueDisplayed: 1.00k  [0603]  (hidden comment: RG1608P-102-B-T5)
R174  ValueDisplayed: 1.0M  [0603]  (hidden comment: CRCW06031M00JNEA)
R175  ValueDisplayed: 1.00k  [0603]  (hidden comment: RG1608P-102-B-T5)
R176  ValueDisplayed: 47  [2512]  (hidden comment: CRCW251247R0JNEG)
R177  ValueDisplayed: 0  [0603]  (hidden comment: CRCW06030000Z0EA)
R178  ValueDisplayed: 1.00k  [0603]  (hidden comment: RG1608P-102-B-T5)
R179  ValueDisplayed: 0  [0603]  (hidden comment: CRCW06030000Z0EA)
R180  ValueDisplayed: 1.0M  [0603]  (hidden comment: CRCW06031M00JNEA)
R181  ValueDisplayed: 0  [0603]  (hidden comment: CRCW06030000Z0EA)
R182  ValueDisplayed: 1.00k  [0603]  (hidden comment: RG1608P-102-B-T5)
R183  ValueDisplayed: 47  [2512]  (hidden comment: CRCW251247R0JNEG)
R184  ValueDisplayed: 0  [0603]  (hidden comment: CRCW06030000Z0EA)
R185  ValueDisplayed: 0  [0603]  (hidden comment: CRCW06030000Z0EA)
R186  ValueDisplayed: 1.00k  [0603]  (hidden comment: RG1608P-102-B-T5)
R187  ValueDisplayed: 1.0M  [0603]  (hidden comment: CRCW06031M00JNEA)
RT5  value 10.0k ohm  [0603]  (hidden comment: ERT-J1VG103FA)
RT6  value 10.0k ohm  [0603]  (hidden comment: ERT-J1VG103FA)
TP-13  5015  [Testpoint_Keystone_Miniature]  (value not drawn)
TP-14  5015  [Testpoint_Keystone_Miniature]  (value not drawn)
TP-15  5015  [Testpoint_Keystone_Miniature]  (value not drawn)
TP-16  5015  [Testpoint_Keystone_Miniature]  (value not drawn)
TP-17  5015  [Testpoint_Keystone_Miniature]  (value not drawn)
TP-18  5015  [Testpoint_Keystone_Miniature]  (value not drawn)
TP-C5  5015  [Testpoint_Keystone_Miniature]  (value not drawn)
TP-C6  5015  [Testpoint_Keystone_Miniature]  (value not drawn)
TP-VPROG3  5015  [Testpoint_Keystone_Miniature]  (value not drawn)
TP-VSS2  5015  [Testpoint_Keystone_Miniature]  (value not drawn)
U3  BQ76PL536ATPAPRQ1  [PAP0064F_N]
Z27  value 36V  [SMA]  (hidden comment: SMAJ36CA)
Z28  value 5.6V  [SOD-123]  (hidden comment: MMSZ5232B-7-F)
Z29  value 5.6V  [SOD-123]  (hidden comment: MMSZ5232B-7-F)
Z30  value 5.6V  [SOD-123]  (hidden comment: MMSZ5232B-7-F)
Z31  value 5.6V  [SOD-123]  (hidden comment: MMSZ5232B-7-F)
Z32  value 5.6V  [SOD-123]  (hidden comment: MMSZ5232B-7-F)
Z33  value 5.6V  [SOD-123]  (hidden comment: MMSZ5232B-7-F)
Z34  value 5.6V  [SOD-123]  (hidden comment: MMSZ5232B-7-F)
Z35  value 5.6V  [SOD-123]  (hidden comment: MMSZ5232B-7-F)
Z36  value 5.6V  [SOD-123]  (hidden comment: MMSZ5232B-7-F)
Z37  value 5.6V  [SOD-123]  (hidden comment: MMSZ5232B-7-F)
Z38  value 5.6V  [SOD-123]  (hidden comment: MMSZ5232B-7-F)
Z39  value 5.6V  [SOD-123]  (hidden comment: MMSZ5232B-7-F)

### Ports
3-ALERT_N, 3-ALERT_S, 3-CELL0, 3-CELL1, 3-CELL2, 3-CELL3, 3-CELL4, 3-CELL5, 3-CELL6, 3-CONV_N, 3-CONV_S, 3-CS_N, 3-CS_S, 3-DRDY_N, 3-DRDY_S, 3-FAULT_N, 3-FAULT_S, 3-LDOA, 3-LDOD1, 3-REG50, 3-SCLK_N, 3-SCLK_S, 3-SDI_N, 3-SDI_S, 3-SDO_N, 3-SDO_S, 3-VBAT

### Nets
3-VC0: C86.2 C88.2 C90.2 C93.2 C98.2 C101.2 C104.2 C105.2 C107.2 C108.2 C109.2 C110.2 C111.2 C112.2 C113.2 C114.2 C115.2 C116.2 C117.2 C118.2 C119.2 Q20.4(S) Q20.7(S) Q22.4(S) Q22.7(S) R181.2 R185.2 R187.1 TP-VSS2.1 U3.13(VC0) U3.14(VSS) U3.15(AGND) U3.25(VSSD) U3.33(VSS) U3.34(VSS) U3.35(VSS) U3.49(VSSD) U3.50(TEST) U3.65(PAD) Z27.1 Z38.2(A) Z39.2(A) ; port 3-CELL0  [also labelled 3-VSS]
3-ALERT_N: U3.57(ALERT_N) ; port 3-ALERT_N
3-ALERT_S: U3.23(ALERT_S) ; port 3-ALERT_S
3-CB1: R186.1 U3.12(CB1)
3-CB2: R178.1 U3.10(CB2)
3-CB3: R173.1 U3.8(CB3)
3-CB4: R162.1 U3.6(CB4)
3-CB5: R157.1 U3.4(CB5)
3-CB6: R153.1 U3.2(CB6)
3-CELL1: C103.2 C113.1 Q21.4(S) Q21.7(S) R180.1 R182.2 R183.2 Z36.2(A) Z37.2(A) Z38.1(K) ; port 3-CELL1
3-CELL2: C100.2 C103.1 Q19.4(S) Q19.7(S) R174.1 R175.2 R176.2 Z34.2(A) Z35.2(A) Z36.1(K) ; port 3-CELL2
3-CELL3: C95.2 C100.1 Q18.4(S) Q18.7(S) R163.1 R164.2 R167.2 Z32.2(A) Z33.2(A) Z34.1(K) ; port 3-CELL3
3-CELL4: C92.2 C95.1 Q17.4(S) Q17.7(S) R158.1 R159.2 R160.2 Z30.2(A) Z31.2(A) Z32.1(K) ; port 3-CELL4
3-CELL5: C89.2 C92.1 Q16.4(S) Q16.7(S) R154.1 R155.2 R156.2 Z28.2(A) Z29.2(A) Z30.1(K) ; port 3-CELL5
3-CELL6: C89.1 J7.1 R150.2 R151.2 TP-C5.1 Z28.1(K) ; port 3-CELL6
3-CONV_N: U3.59(CONV_N) ; port 3-CONV_N
3-CONV_S: C111.1 U3.21(CONV_S) ; port 3-CONV_S
3-CS_N: U3.52(CS_N) ; port 3-CS_N
3-CS_S: C110.1 U3.29(CS_S) ; port 3-CS_S
3-DRDY_N: U3.58(DRDY_N) ; port 3-DRDY_N
3-DRDY_S: U3.22(DRDY_S) ; port 3-DRDY_S
3-FAULT_N: U3.56(FAULT_N) ; port 3-FAULT_N
3-FAULT_S: U3.24(FAULT_S) ; port 3-FAULT_S
3-LDOA: C116.1 C117.1 U3.17(LDOA) ; port 3-LDOA
3-LDOD1: C118.1 C119.1 R172.2 TP-VPROG3.1 U3.18(LDOD1) U3.46(LDOD2) ; port 3-LDOD1
3-REG50: C96.1 C97.1 C115.1 J8.2 J9.2 R161.2 R168.2 R177.1 RT5.2 RT6.2 U3.32(REG50) ; port 3-REG50
3-SCLK_N: U3.55(SCLK_N) ; port 3-SCLK_N
3-SCLK_S: C108.1 U3.26(SCLK_S) ; port 3-SCLK_S
3-SDI_N: U3.53(SDI_N) ; port 3-SDI_N
3-SDI_S: C109.1 U3.28(SDI_S) ; port 3-SDI_S
3-SDO_N: U3.54(SDO_N) ; port 3-SDO_N
3-SDO_S: R177.2 U3.27(SDO_S) ; port 3-SDO_S
3-VBAT: C88.1 C114.1 R152.2 U3.63(BAT1) U3.64(BAT2) Z27.2 ; port 3-VBAT
3-VC1: C102.2 C107.1 R182.1 U3.11(VC1)
3-VC2: C99.2 C101.1 C102.1 R175.1 U3.9(VC2)
3-VC3: C94.2 C98.1 C99.1 R164.1 U3.7(VC3)
3-VC4: C91.2 C93.1 C94.1 R159.1 U3.5(VC4)
3-VC5: C87.2 C90.1 C91.1 R155.1 U3.3(VC5)
3-VC6: C86.1 C87.1 R151.1 U3.1(VC6)
NetC96_2: C96.2 R165.1 R169.2 TP-14.1 U3.20(TS1+)
NetC97_2: C97.2 R166.1 R170.2 TP-16.1 U3.61(TS2+)
NetC104_1: C104.1 C106.2 R184.1 R185.1 U3.47(GPAI-)
NetC105_1: C105.1 C106.1 R179.1 R181.1 U3.48(GPAI+)
NetC112_1: C112.1 U3.16(VREF)
NetD3_1: D3.1(A) R161.1
NetD3_2: D3.2(K) Q20.1(D) Q20.2(D) Q20.5(D) Q20.6(D) Q20.8(D)
NetJ7_2: J7.2 R152.1 TP-C6.1
NetJ8_1: J8.1 R165.2 RT5.1
NetJ9_1: J9.1 R166.2 RT6.1
NetQ16_1: Q16.1(D) Q16.2(D) Q16.5(D) Q16.6(D) Q16.8(D) R150.1
NetQ16_3: Q16.3(G) R153.2 R154.2 Z29.1(K)
NetQ17_1: Q17.1(D) Q17.2(D) Q17.5(D) Q17.6(D) Q17.8(D) R156.1
NetQ17_3: Q17.3(G) R157.2 R158.2 Z31.1(K)
NetQ18_1: Q18.1(D) Q18.2(D) Q18.5(D) Q18.6(D) Q18.8(D) R160.1
NetQ18_3: Q18.3(G) R162.2 R163.2 Z33.1(K)
NetQ19_1: Q19.1(D) Q19.2(D) Q19.5(D) Q19.6(D) Q19.8(D) R167.1
NetQ19_3: Q19.3(G) R173.2 R174.2 Z35.1(K)
NetQ20_3: Q20.3(G) R171.2
NetQ21_1: Q21.1(D) Q21.2(D) Q21.5(D) Q21.6(D) Q21.8(D) R176.1
NetQ21_3: Q21.3(G) R178.2 R180.2 Z37.1(K)
NetQ22_1: Q22.1(D) Q22.2(D) Q22.5(D) Q22.6(D) Q22.8(D) R183.1
NetQ22_3: Q22.3(G) R186.2 R187.2 Z39.1(K)
NetR168_1: R168.1 R171.1 U3.45(GPIO)
NetR169_1: R169.1 TP-15.1 U3.19(TS1-)
NetR170_1: R170.1 TP-13.1 U3.60(TS2-)
NetR172_1: R172.1 U3.44(HSEL)
NetR179_2: R179.2 TP-17.1
NetR184_2: R184.2 TP-18.1

Not connected (* = marked no-connect by the designer): U3 30(NC)* 31(AUX)* 36(CONV_H) 37(DRDY_H) 38(ALERT_H) 39(FAULT_H) 40(SCLK_H) 41(SDO_H) 42(SDI_H) 43(CS_H) 51(NC)* 62(NC)*

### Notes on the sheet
- (near RT5) T1
- (near RT6) T2

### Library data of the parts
C86 C89 C90 C92 C93 C95 C98 C100 C101 C107 C113 C114 C116 C118 = 06035C104KAT2A: as C48 on sheet PWR763A_3
C87 C88 C91 C94 C99 C102 C103 = GRM188R72A104KA35D: as C49 on sheet PWR763A_3
C96 C97 = GRM188R71C473KA01D: as C58 on sheet PWR763A_3
C104-C106 = C0603C104K4RACTU: as C70-C72 on sheet PWR763A_3
C108-C111 = GRM1885C1H330JA01D: as C62-C65 on sheet PWR763A_3
C112 = C2012X7R1A106M125AC: as C77 on sheet PWR763A_3
C115 C117 C119 = GRM21BR71A225KA01L: as C81 on sheet PWR763A_3
D3 = APT1608SYCK: as D2 on sheet PWR763A_3
J7-J9 = PEC02SAAN: as J4-J6 on sheet PWR763A_3
Q16-Q22 = CSD16301Q2: as Q9-Q15 on sheet PWR763A_3
R150 R156 R160 R167 R176 R183 = CRCW251247R0JNEG: as R113 on sheet PWR763A_3
R151 R153 R155 R157 R159 R162 R164 R173 R175 R178 R182 R186 = RG1608P-102-B-T5: as R114 on sheet PWR763A_3
R152 = CRCW08050000Z0EA: as R115 on sheet PWR763A_3
R154 R158 R163 R174 R180 R187 = CRCW06031M00JNEA: as R117 on sheet PWR763A_3
R161 = CRCW06031K60JNEA: as R123 on sheet PWR763A_3
R165 R166 = CRCW06031K47FKEA: as R127 on sheet PWR763A_3
R168 R172 = CRCW0603100KFKEA: as R126 on sheet PWR763A_3
R169 R170 = CRCW06031K82FKEA: as R132 on sheet PWR763A_3
R171 = CRCW0603100RJNEA: as R130 on sheet PWR763A_3
R177 R179 R181 R184 R185 = CRCW06030000Z0EA: as R140 on sheet PWR763A_3
RT5 RT6 = ERT-J1VG103FA: as RT3 on sheet PWR763A_3
TP-13-TP-18 TP-C5 TP-C6 TP-VPROG3 TP-VSS2 = 5015: as TP-7-TP-12 on sheet PWR763A_3
U3 = BQ76PL536ATPAPRQ1: as U2 on sheet PWR763A_3
Z27 = SMAJ36CA: as Z15 on sheet PWR763A_3
Z28-Z39 = MMSZ5232B-7-F: as Z14 on sheet PWR763A_3

## Sheet PWR763A_5.SchDoc: PWR763A
size 431 x 279 mm; Date: Not shown in title block; ApprovedBy: Not shown in title block; CheckedBy: Not shown in title block; Author: Not shown in title block; CompanyName: Not shown in title block; Engineer: Not shown in title block; Organization: Not shown in title block; Address1: Not shown in title block; Address2: Not shown in title block; Address3: Not shown in title block; Address4: Not shown in title block; DocumentNumber: 1; Revision: Use project parameter SCH_Rev; SheetNumber: 5; SheetTotal: 6; PageSetup: Record=PageOptions¦CenterHorizontal=True¦CenterVertical=True¦PrintScale=1.00¦XCorrection=1.00¦YCorrection=1.00¦PrintKind=0¦BorderSize=5000000¦LeftOffset=0¦BottomOffset=0¦Orientation=2¦PaperLength=1000¦PaperWidth=1000¦Scale=100¦PaperSource=15¦PrintQuality=600¦MediaType=1¦DitherType=10¦PaperKind=Letter¦PrintScaleMode=1
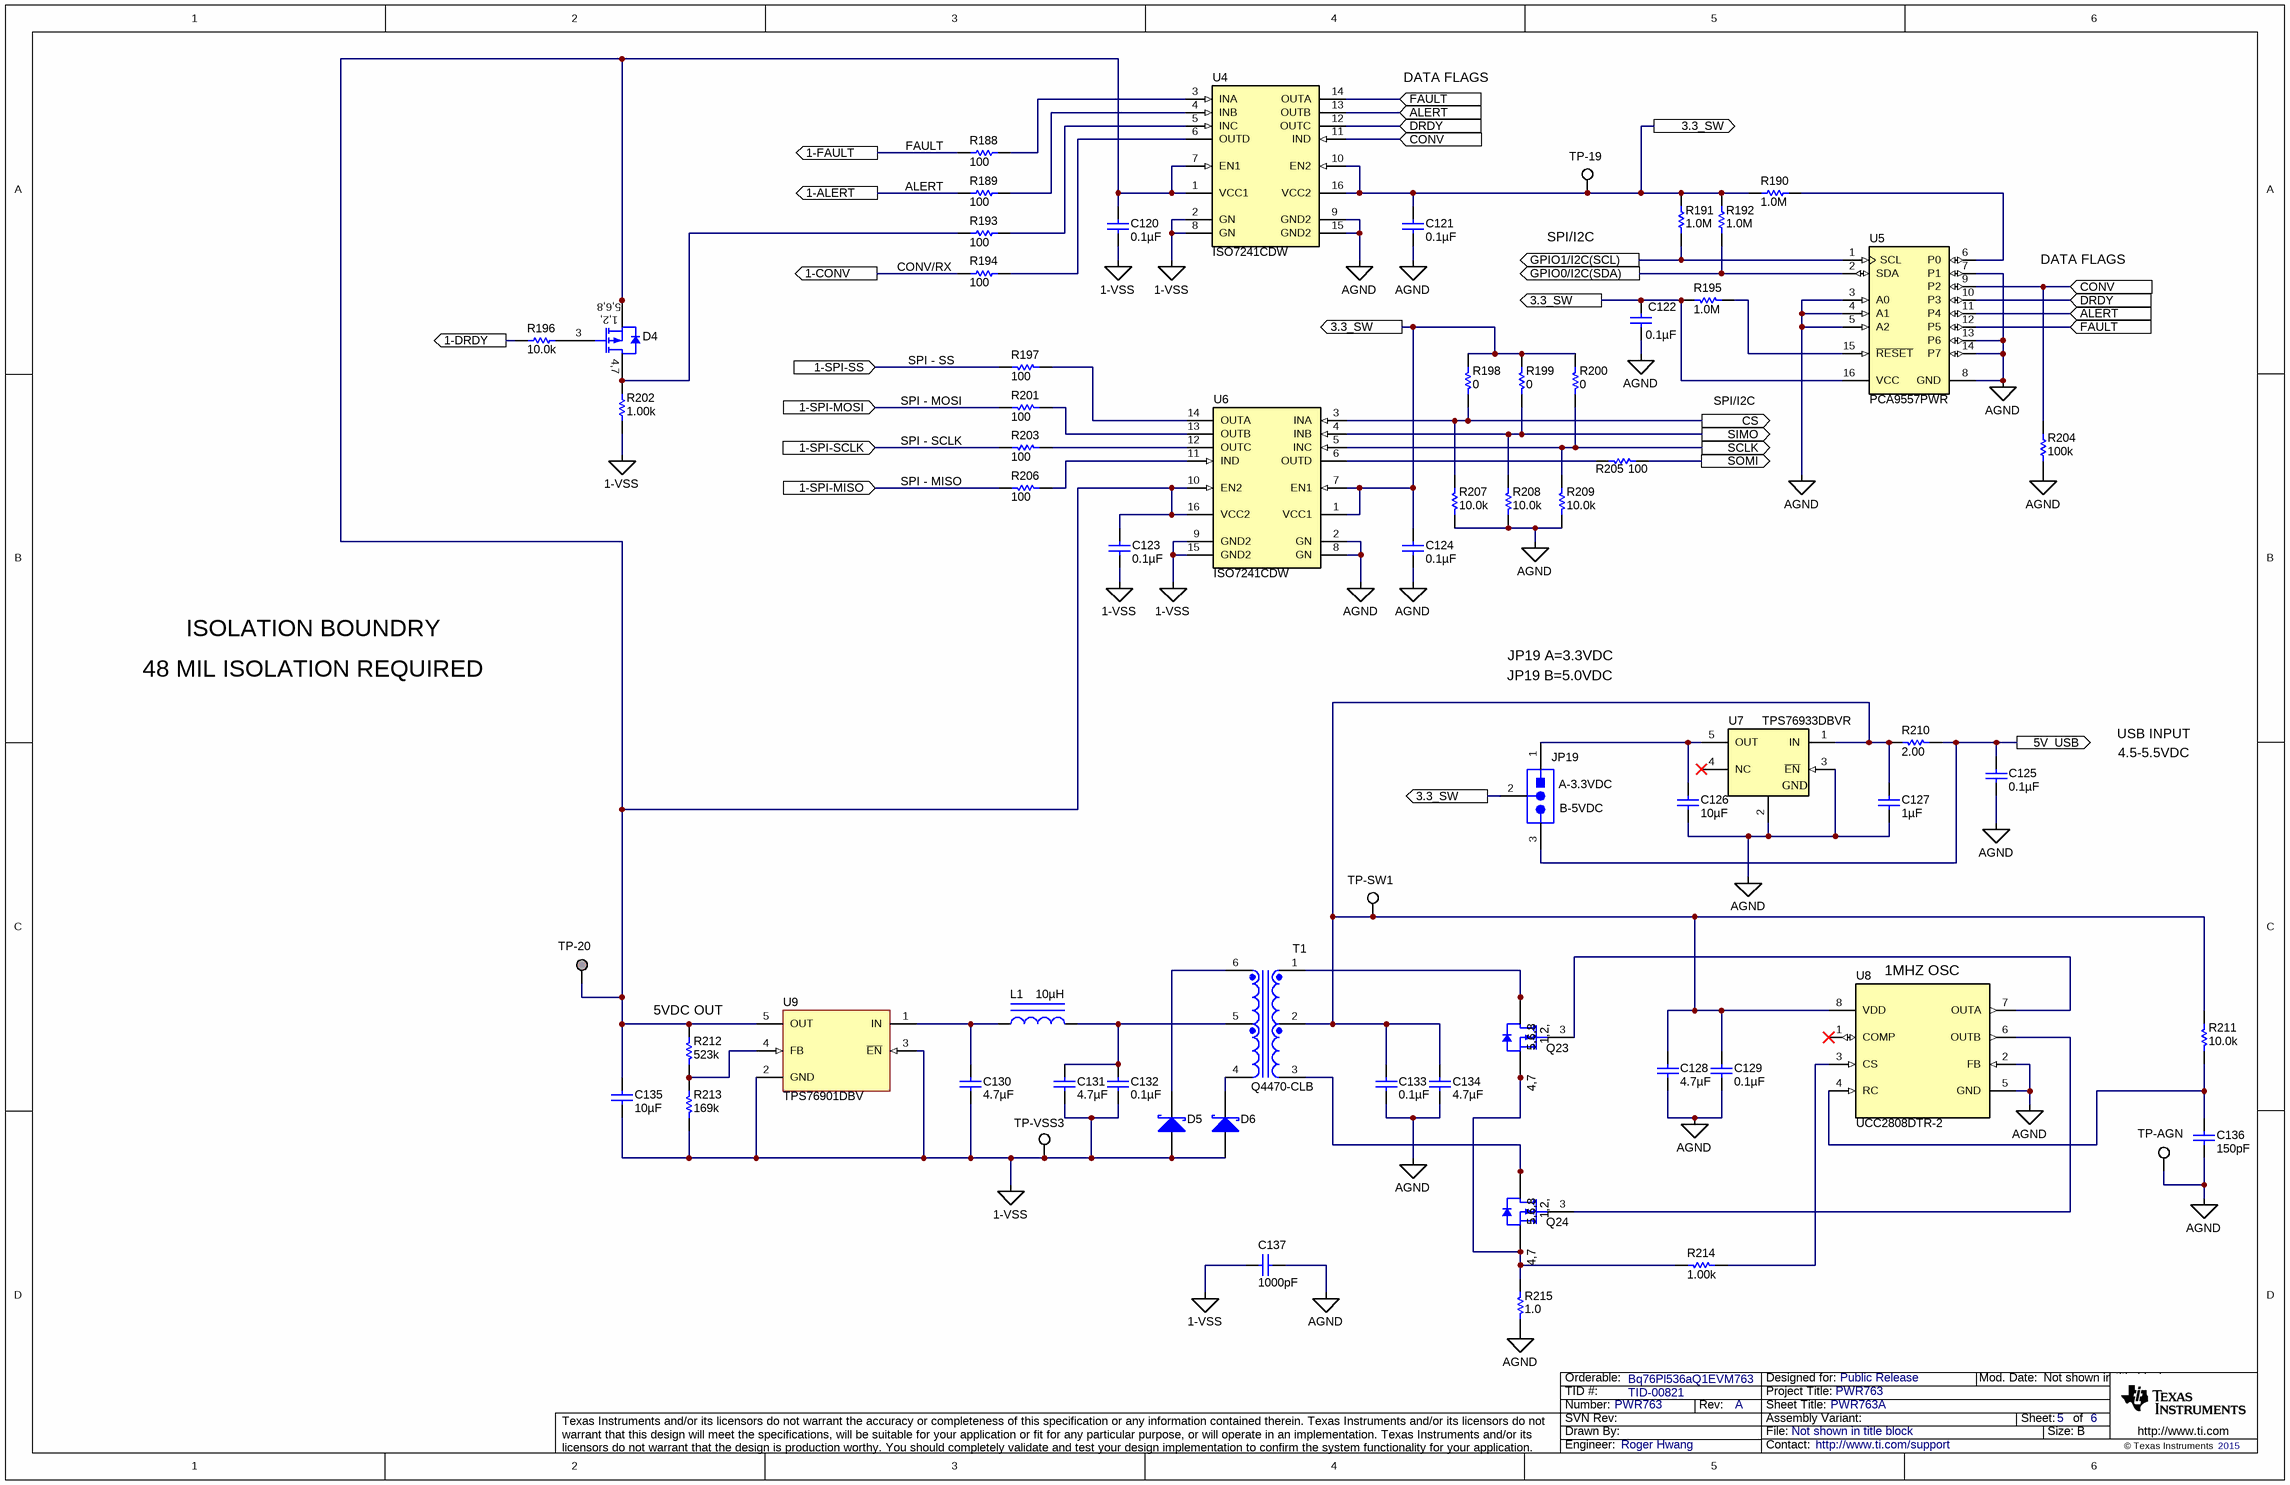
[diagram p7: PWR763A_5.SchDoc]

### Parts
C120  ValueDisplayed: 0.1µF  [0603]  (hidden comment: 06035C104KAT2A)
C121  ValueDisplayed: 0.1µF  [0603]  (hidden comment: 06035C104KAT2A)
C122  ValueDisplayed: 0.1µF  [0603]  (hidden comment: 06035C104KAT2A)
C123  ValueDisplayed: 0.1µF  [0603]  (hidden comment: 06035C104KAT2A)
C124  ValueDisplayed: 0.1µF  [0603]  (hidden comment: 06035C104KAT2A)
C125  ValueDisplayed: 0.1µF  [0603]  (hidden comment: 06035C104KAT2A)
C126  ValueDisplayed: 10µF  [0805_145]  (hidden comment: C2012X7R1A106M125AC)
C127  ValueDisplayed: 1µF  [0603]  (hidden comment: C1608X7R1C105K)
C128  ValueDisplayed: 4.7µF  [0603]  (hidden comment: C0603C475K8PACTU)
C129  ValueDisplayed: 0.1µF  [0603]  (hidden comment: 06035C104KAT2A)
C130  ValueDisplayed: 4.7µF  [0603]  (hidden comment: C0603C475K8PACTU)
C131  ValueDisplayed: 4.7µF  [0603]  (hidden comment: C0603C475K8PACTU)
C132  ValueDisplayed: 0.1µF  [0603]  (hidden comment: 06035C104KAT2A)
C133  ValueDisplayed: 0.1µF  [0603]  (hidden comment: 06035C104KAT2A)
C134  ValueDisplayed: 4.7µF  [0603]  (hidden comment: C0603C475K8PACTU)
C135  ValueDisplayed: 10µF  [0805_145]  (hidden comment: C2012X7R1A106M125AC)
C136  ValueDisplayed: 150pF  [0603]  (hidden comment: C0603C151J5GACTU)
C137  ValueDisplayed: 1000pF  [CAPRD750W60D700H1000]  (hidden comment: DEBE33F102ZC3B)
D4  CSD25310Q2  [TRANS_NexFET_Q2]  (value not drawn)
D5  BAT54HT1G  [sod-323]  (value not drawn)
D6  BAT54HT1G  [sod-323]  (value not drawn)
JP19  PEC03SAAN  [CONN_PEC03SAAN]  (value not drawn)
L1  ValueDisplayed: 10µH  [0805_HV]  (hidden comment: LB2012T100KR)
Q23  CSD16301Q2  [TRANS_NexFET_Q2]  (value not drawn)
Q24  CSD16301Q2  [TRANS_NexFET_Q2]  (value not drawn)
R188  ValueDisplayed: 100  [0603]  (hidden comment: CRCW0603100RJNEA)
R189  ValueDisplayed: 100  [0603]  (hidden comment: CRCW0603100RJNEA)
R190  ValueDisplayed: 1.0M  [0603]  (hidden comment: CRCW06031M00JNEA)
R191  ValueDisplayed: 1.0M  [0603]  (hidden comment: CRCW06031M00JNEA)
R192  ValueDisplayed: 1.0M  [0603]  (hidden comment: CRCW06031M00JNEA)
R193  ValueDisplayed: 100  [0603]  (hidden comment: CRCW0603100RJNEA)
R194  ValueDisplayed: 100  [0603]  (hidden comment: CRCW0603100RJNEA)
R195  ValueDisplayed: 1.0M  [0603]  (hidden comment: CRCW06031M00JNEA)
R196  ValueDisplayed: 10.0k  [0603]  (hidden comment: ERJ-3EKF1002V)
R197  ValueDisplayed: 100  [0603]  (hidden comment: CRCW0603100RJNEA)
R198  ValueDisplayed: 0  [0603]  (hidden comment: CRCW06030000Z0EA)
R199  ValueDisplayed: 0  [0603]  (hidden comment: CRCW06030000Z0EA)
R200  ValueDisplayed: 0  [0603]  (hidden comment: CRCW06030000Z0EA)
R201  ValueDisplayed: 100  [0603]  (hidden comment: CRCW0603100RJNEA)
R202  ValueDisplayed: 1.00k  [0603]  (hidden comment: RG1608P-102-B-T5)
R203  ValueDisplayed: 100  [0603]  (hidden comment: CRCW0603100RJNEA)
R204  ValueDisplayed: 100k  [0603]  (hidden comment: CRCW0603100KFKEA)
R205  ValueDisplayed: 100  [0603]  (hidden comment: CRCW0603100RJNEA)
R206  ValueDisplayed: 100  [0603]  (hidden comment: CRCW0603100RJNEA)
R207  ValueDisplayed: 10.0k  [0603]  (hidden comment: ERJ-3EKF1002V)
R208  ValueDisplayed: 10.0k  [0603]  (hidden comment: ERJ-3EKF1002V)
R209  ValueDisplayed: 10.0k  [0603]  (hidden comment: ERJ-3EKF1002V)
R210  ValueDisplayed: 2.00  [0603]  (hidden comment: RC0603FR-072RL)
R211  ValueDisplayed: 10.0k  [0603]  (hidden comment: ERJ-3EKF1002V)
R212  ValueDisplayed: 523k  [0603]  (hidden comment: RC0603FR-07523KL)
R213  ValueDisplayed: 169k  [0603]  (hidden comment: RC0603FR-07169KL)
R214  ValueDisplayed: 1.00k  [0603]  (hidden comment: RG1608P-102-B-T5)
R215  ValueDisplayed: 1.0  [0603]  (hidden comment: CRCW06031R00JNEA)
T1  Q4470-CLB  [Coilcraft_Q4470-CL]
TP-19  5015  [Testpoint_Keystone_Miniature]  (value not drawn)
TP-20  5020  [Testpoint_Keystone_Miniature]  (value not drawn)  (no BOM)
TP-AGN  5015  [Testpoint_Keystone_Miniature]  (value not drawn)
TP-SW1  5015  [Testpoint_Keystone_Miniature]  (value not drawn)
TP-VSS3  5015  [Testpoint_Keystone_Miniature]  (value not drawn)
U4  ISO7241CDW  [DW0016A_N]
U5  PCA9557PWR  [PW0016A_N]
U6  ISO7241CDW  [DW0016A_N]
U7  TPS76933DBVR  [DBV0005A_N]
U8  UCC2808DTR-2  [D0008A_N]
U9  TPS76901DBV  [DBV0005A_N]

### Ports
1-ALERT, 1-CONV, 1-DRDY, 1-FAULT, 1-SPI-MISO, 1-SPI-MOSI, 1-SPI-SCLK, 1-SPI-SS, 3.3_SW, 5V_USB, ALERT, CONV, CS, DRDY, FAULT, GPIO0/I2C(SDA), GPIO1/I2C(SCL), SCLK, SIMO, SOMI

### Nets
1-VSS: C120.2 C123.2 C130.2 C131.2 C132.2 C135.2 C137.2 D5.2(A) D6.2(A) R202.1 R213.1 TP-VSS3.1 U4.2(GN) U4.8(GN) U6.9(GND2) U6.15(GND2) U9.2(GND) U9.3(~{EN})  [project net 1-VC0]
AGND: C121.2 C122.2 C124.2 C125.2 C126.2 C127.2 C128.2 C129.2 C133.2 C134.2 C136.2 C137.1 R204.1 R207.1 R208.1 R209.1 R215.1 TP-AGN.1 U4.9(GND2) U4.15(GND2) U5.3(A0) U5.4(A1) U5.5(A2) U5.7(P1) U5.8(GND) U5.13(P6) U5.14(P7) U6.2(GN) U6.8(GN) U7.2(GND) U7.3(~{EN}) U8.2(FB) U8.5(GND)
1-ALERT: R189.1 ; port 1-ALERT
1-CONV: R194.1 ; port 1-CONV
1-DRDY: R196.1 ; port 1-DRDY
1-FAULT: R188.1 ; port 1-FAULT
1-SPI-MISO: R206.2 ; port 1-SPI-MISO
1-SPI-MOSI: R201.2 ; port 1-SPI-MOSI
1-SPI-SCLK: R203.2 ; port 1-SPI-SCLK
1-SPI-SS: R197.2 ; port 1-SPI-SS
3.3_SW: C121.1 C122.1 C124.1 JP19.2 R190.2 R191.2 R192.2 R195.2 R198.2 R199.2 R200.2 TP-19.1 U4.10(EN2) U4.16(VCC2) U5.16(VCC) U6.1(VCC1) U6.7(EN1) ; port 3.3_SW
5V_USB: C125.1 JP19.3 R210.1 ; port 5V_USB
ALERT: U4.13(OUTB) U5.11(P4) ; port ALERT
CONV: R204.2 U4.11(IND) U5.9(P2) ; port CONV
CS: R198.1 R207.2 U6.3(INA) ; port CS
DRDY: U4.12(OUTC) U5.10(P3) ; port DRDY
FAULT: U4.14(OUTA) U5.12(P5) ; port FAULT
GPIO0/I2C(SDA): R192.1 U5.2(SDA) ; port GPIO0/I2C(SDA)
GPIO1/I2C(SCL): R191.1 U5.1(SCL) ; port GPIO1/I2C(SCL)
SCLK: R200.1 R209.2 U6.5(INC) ; port SCLK
SIMO: R199.1 R208.2 U6.4(INB) ; port SIMO
SOMI: R205.1 ; port SOMI
NetC120_1: C120.1 C123.1 C135.1 D4.1(S) D4.2(S) D4.5(S) D4.6(S) D4.8(S) R212.1 TP-20.1 U4.1(VCC1) U4.7(EN1) U6.10(EN2) U6.16(VCC2) U9.5(OUT)
NetC126_1: C126.1 JP19.1 U7.5(OUT)
NetC127_1: C127.1 C128.1 C129.1 C133.1 C134.1 R210.2 R211.1 T1.2 TP-SW1.1 U7.1(IN) U8.8(VDD)
NetC130_1: C130.1 L1.2 U9.1(IN)
NetC131_1: C131.1 C132.1 L1.1 T1.5
NetC136_1: C136.1 R211.2 U8.4(RC)
NetD4_3: D4.3(G) R196.2
NetD4_4: D4.4(D) D4.7(D) R193.1 R202.2
NetD5_1: D5.1(K) T1.6
NetD6_1: D6.1(K) T1.4
NetQ23_1: Q23.1(D) Q23.2(D) Q23.5(D) Q23.6(D) Q23.8(D) T1.1
NetQ23_3: Q23.3(G) U8.7(OUTA)
NetQ23_4: Q23.4(S) Q23.7(S) Q24.4(S) Q24.7(S) R214.2 R215.2
NetQ24_1: Q24.1(D) Q24.2(D) Q24.5(D) Q24.6(D) Q24.8(D) T1.3
NetQ24_3: Q24.3(G) U8.6(OUTB)
NetR188_2: R188.2 U4.3(INA)
NetR189_2: R189.2 U4.4(INB)
NetR190_1: R190.1 U5.6(P0)
NetR193_2: R193.2 U4.5(INC)
NetR194_2: R194.2 U4.6(OUTD)
NetR195_1: R195.1 U5.15(~{RESET})
NetR197_1: R197.1 U6.14(OUTA)
NetR201_1: R201.1 U6.13(OUTB)
NetR203_1: R203.1 U6.12(OUTC)
NetR205_2: R205.2 U6.6(OUTD)
NetR206_1: R206.1 U6.11(IND)
NetR212_2: R212.2 R213.2 U9.4(FB)
NetR214_1: R214.1 U8.3(CS)

Not connected (* = marked no-connect by the designer): U7 4(NC)*; U8 1(COMP)*

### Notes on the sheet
- DATA FLAGS
- (near R188) FAULT
- ALERT
- (near TP-19) SPI/I2C
- CONV/RX
- SPI - SS
- SPI - MOSI
- SPI - SCLK
- SPI/I2C
- SPI - MISO
- ISOLATION BOUNDRY
- 48 MIL ISOLATION REQUIRED
- JP19 A=3.3VDC
- JP19 B=5.0VDC
- USB INPUT
- 4.5-5.5VDC
- (near JP19) B-5VDC
- (near JP19) A-3.3VDC
- (near U8) 1MHZ OSC
- (near R212) 5VDC OUT

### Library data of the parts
C120-C125 C129 C132 C133 = 06035C104KAT2A: as C48 on sheet PWR763A_3
C126 C135 = C2012X7R1A106M125AC: as C77 on sheet PWR763A_3
C127 = C1608X7R1C105K: CAP, CERM, 1 µF, 16 V, +/- 10%, X7R, 0603; Manufacturer: TDK; Polarized: N; CompType: Capacitor; Value: 1uF; U/M: EA; Cap_F: 0.000001; Tolerance_%: 10; ESR_ohm: 0.0057; Value1: 0.0057 ohm; VDC_V: 16; Value2: 16V; TaMin_C: -55; TaMax_C: 125
C128 C130 C131 C134 = C0603C475K8PACTU: CAP, CERM, 4.7 µF, 10 V, +/- 10%, X5R, 0603; Manufacturer: Kemet; Polarized: N; CompType: Capacitor; Value: 4.7uF; U/M: EA; Cap_F: 0.0000047; Tolerance_%: 10; ESR_ohm: 0.006; Value1: 0.006 ohm; Value2: 10V; IRMS_A: 7.24; TaMin_C: -55; TaMax_C: 85
C136 = C0603C151J5GACTU: CAP, CERM, 150 pF, 50 V, +/- 5%, C0G/NP0, 0603; Manufacturer: Kemet; Polarized: N; CompType: Capacitor; Value: 150pF; U/M: EA; Cap_F: 0.00000000015; Tolerance_%: 5; Value1: Unknown; VDC_V: 50; Value2: 50V; TaMin_C: -55; TaMax_C: 125
C137 = DEBE33F102ZC3B: CAP, CERM, 1000 pF, 3150 V, +80/-20%, E, Radial Disc D7x6mm; Manufacturer: MuRata; Polarized: N; CompType: Capacitor; Value: 1000pF; U/M: EA; Cap_F: 0.000000001; Tolerance_%: 80; Value1: Unknown; VDC_V: 3150; Value2: 3150V; TaMin_C: -25; TaMax_C: 85; Cap_Case: Disc, 7x6mm
D4 = CSD25310Q2: MOSFET, P-CH, -20 V, -20 A, SON 2x2mm; Manufacturer: Texas Instruments; Alternate Manufacturer: None; SymbolCreator: a0411947; U/M: EA; ChType: P; Value: -20V; Value1: 0.0239 ohm; Rdson45_ohm: 0.0239; Value2: 3.6 nC; QgTyp_nC: 3.6; Vgs_V: 8; AEC Category: Q101
D5 D6 = BAT54HT1G: Diode, Schottky, 30 V, 0.2 A, SOD-323; Manufacturer: ON Semiconductor; U/M: EA; Vf_V: 0.35; Value: 30V; Value1: 0.2A; Value2: 0.35V; Io_A: 0.2; Vr_V: 30
JP19 = PEC03SAAN: Header, 100mil, 3x1, Tin, TH; Manufacturer: Sullins Connector Solutions; SymbolCreator: a0799628; U/M: EA
L1 = LB2012T100KR: Inductor, Wirewound, Ferrite, 10uH, 0.12A, 0.5 ohm, SMD; Manufacturer: Taiyo Yuden; Ind_H: 10.0E-6; Imax_A: 0.12; Irms: 0.12A @ C rise; Isat: 0.12A @ % inductance drop; DCR_ohm: 0.5; Value1: 0.5 ohm; U/M: EA
Q23 Q24 = CSD16301Q2: as Q9-Q15 on sheet PWR763A_3
R188 R189 R193 R194 R197 R201 R203 R205 R206 = CRCW0603100RJNEA: as R130 on sheet PWR763A_3
R190-R192 R195 = CRCW06031M00JNEA: as R117 on sheet PWR763A_3
R196 R207-R209 R211 = ERJ-3EKF1002V: RES, 10.0 k, 1%, 0.1 W, 0603; Manufacturer: Panasonic; CompType: Resistor; Value: 10.0k; Res_ohm: 10000; Value_Code: 10k0; Tolerance_%: 1; Power_W: 0.1; Value2: 0.1W; VDC_V: 75; TempCo: 100 ppm/C; EIA_Code: E96; U/M: EA
R198-R200 = CRCW06030000Z0EA: as R140 on sheet PWR763A_3
R202 R214 = RG1608P-102-B-T5: as R114 on sheet PWR763A_3
R204 = CRCW0603100KFKEA: as R126 on sheet PWR763A_3
R210 = RC0603FR-072RL: RES, 2.00, 1%, 0.1 W, 0603; Manufacturer: Yageo America; CompType: Resistor; Value: 2.00; Res_ohm: 2; Value_Code: 2R00; Tolerance_%: 1; Power_W: 0.1; Value2: 0.1W; VDC_V: 150; TempCo: 200 ppm/C; EIA_Code: E96; U/M: EA
R212 = RC0603FR-07523KL: RES, 523 k, 1%, 0.1 W, 0603; Manufacturer: Yageo America; CompType: Resistor; Value: 523k; Res_ohm: 523000; Tolerance_%: 1; Power_W: 0.1; Value2: 0.1W; VDC_V: 150; TempCo: 200 ppm/C; EIA_Code: E96; U/M: EA
R213 = RC0603FR-07169KL: RES, 169 k, 1%, 0.1 W, 0603; Manufacturer: Yageo America; CompType: Resistor; Value: 169k; Res_ohm: 169000; Tolerance_%: 1; Power_W: 0.1; Value2: 0.1W; VDC_V: 150; TempCo: 200 ppm/C; EIA_Code: E96; U/M: EA
R215 = CRCW06031R00JNEA: RES, 1.0, 5%, 0.1 W, 0603; Manufacturer: Vishay-Dale; CompType: Resistor; Value: 1.0; Res_ohm: 1; Value_Code: 1R00; Tolerance_%: 5; Power_W: 0.1; Value2: 0.1W; VDC_V: 75; TempCo: 200 ppm/C; EIA_Code: E24; U/M: EA
T1 = Q4470-CLB: Transformer, 400 uH, SMT; Manufacturer: Coilcraft; SymbolCreator: Altium; DCR_Ohm: 0.95; Value: 400 uH; U/M: EA
TP-19 TP-AGN TP-SW1 TP-VSS3 = 5015: as TP-7-TP-12 on sheet PWR763A_3
TP-20 = 5020: LOW PROFILE, TH; Manufacturer: Keystone; CompType: Standoff
U4 U6 = ISO7241CDW: 25 Mbps Quad Channels, 3 / 1, Digital Isolator, 3.3 V / 5 V, -40 to +125 degC, 16-pin SOIC (DW), Green (RoHS & no Sb/Br); Manufacturer: Texas Instruments; Alternate PartNumber: Equivalent; Datarate(Mbps): 25; Input Noise Filter: Yes; Insulation Rating(VRMS): 2500; Prop Delay(Max)(ns): 42; Rating: Catalog; Supply Voltage(s)(V): 3.3, 5; TTL/CMOS Input Threshold: TTL
U5 = PCA9557PWR: Remote 8-Bit I2C and SMBus Low-Power I/O Expander with Reset and Configuration Registers, 2.3 to 5.5 V, -40 to 85 degC, 16-pin TSSOP (PW), Green (RoHS & no Sb/Br); Manufacturer: Texas Instruments; Alternate PartNumber: Equivalent; SubFamily: I2C IO Expander; No. of Outputs: 8; Reset Input: Yes; fSCLK(Max)(MHz): 400; VCC(Min)(V): 2.3; VCC(Max)(V): 5.5; I2C Address: 0011 xxx
U7 = TPS76933DBVR: Single Output LDO, 100 mA, Fixed 3.3 V Output, 2.7 to 10 V Input, with Low IQ, 5-pin SOT-23 (DBV), -40 to 125 degC, Green (RoHS & no Sb/Br); Manufacturer: Texas Instruments; Alternate PartNumber: Equivalent; Accuracy(%): 3; Fixed Output Options(V): 3.3; Iout(Max)(A): 0.1; Iq(Typ)(mA): 0.02; Rating: Catalog; SubFamily: Single Channel LDO; Vdo(Typ)(mV): 98; Vin(Max)(V): 10; Vin(Min)(V): 2.7
U8 = UCC2808DTR-2: LOW POWER CURRENT MODE PUSH-PULL PWM, D0008A; Alternate PartNumber: UCC2808D-2; Manufacturer: Texas Instruments; SymbolCreator: Altium; CompType: IC; U/M: EA
U9 = TPS76901DBV: Ultralow-Power 100-mA Low-Dropout Linear Regulators, DBV0005A; Manufacturer: Texas Instruments; SymbolCreator: a0411947; CompType: IC; U/M: EA

## Sheet PWR763A_Hardware.SchDoc: PWR763A
size 431 x 279 mm; Date: Not shown in title block; ApprovedBy: Not shown in title block; CheckedBy: Not shown in title block; Author: Not shown in title block; CompanyName: Not shown in title block; Engineer: Not shown in title block; Organization: Not shown in title block; Address1: Not shown in title block; Address2: Not shown in title block; Address3: Not shown in title block; Address4: Not shown in title block; DocumentNumber: 1; Revision: Use project parameter SCH_Rev; SheetNumber: 6; SheetTotal: 6; PageSetup: Record=PageOptions¦CenterHorizontal=True¦CenterVertical=True¦PrintScale=1.00¦XCorrection=1.00¦YCorrection=1.00¦PrintKind=0¦BorderSize=5000000¦LeftOffset=0¦BottomOffset=0¦Orientation=2¦PaperLength=1000¦PaperWidth=1000¦Scale=100¦PaperSource=15¦PrintQuality=600¦MediaType=1¦DitherType=10¦PaperKind=Letter¦PrintScaleMode=1
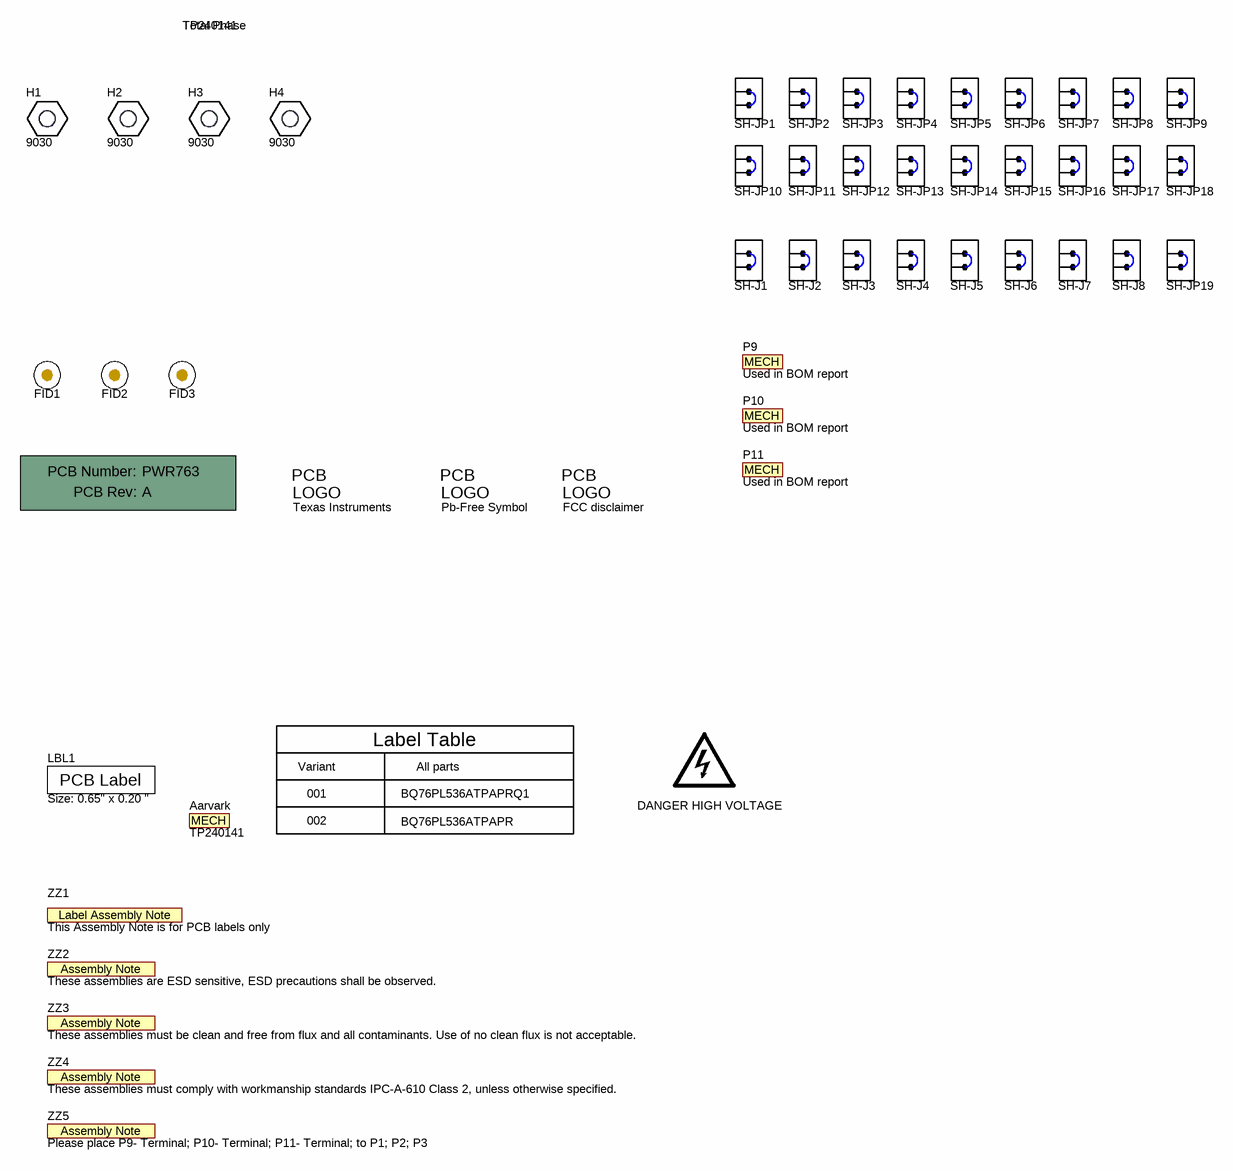
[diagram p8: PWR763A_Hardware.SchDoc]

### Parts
!PCB1  Printed Circuit Board  (value not drawn)  (mechanical)
Aarvark  TP240141  Manufacturer: Total Phase  (mechanical)
CAUTION_1  DANGER HIGH VOLTAGE  [IEC_HighVoltage_Small]  (no BOM)
FID1  Fiducial  [Fiducial10-20]  (value not drawn)
FID2  Fiducial  [Fiducial10-20]  (value not drawn)
FID3  Fiducial  [Fiducial10-20]  (value not drawn)
H1  9030  [Keystone_9030]
H2  9030  [Keystone_9030]
H3  9030  [Keystone_9030]
H4  9030  [Keystone_9030]
LBL1  Size: 0.65" x 0.20 "  [Label_650x200]
Logo1  Texas Instruments  [TI_Stacked_Overlay_Small]  (no BOM)
Logo2  Pb-Free Symbol  [Pb-Free_Overlay_Small]  (no BOM)
Logo3  FCC disclaimer  [FCC_disclaimer]  (no BOM)
P9  Used in BOM report  (mechanical)
P10  Used in BOM report  (mechanical)
P11  Used in BOM report  (mechanical)
SH-J1  969102-0000-DA  [SNT-100-BK-G]  (value not drawn)
SH-J2  969102-0000-DA  [SNT-100-BK-G]  (value not drawn)
SH-J3  969102-0000-DA  [SNT-100-BK-G]  (value not drawn)
SH-J4  969102-0000-DA  [SNT-100-BK-G]  (value not drawn)
SH-J5  969102-0000-DA  [SNT-100-BK-G]  (value not drawn)
SH-J6  969102-0000-DA  [SNT-100-BK-G]  (value not drawn)
SH-J7  969102-0000-DA  [SNT-100-BK-G]  (value not drawn)
SH-J8  969102-0000-DA  [SNT-100-BK-G]  (value not drawn)
SH-JP1  969102-0000-DA  [SNT-100-BK-G]  (value not drawn)
SH-JP2  969102-0000-DA  [SNT-100-BK-G]  (value not drawn)
SH-JP3  969102-0000-DA  [SNT-100-BK-G]  (value not drawn)
SH-JP4  969102-0000-DA  [SNT-100-BK-G]  (value not drawn)
SH-JP5  969102-0000-DA  [SNT-100-BK-G]  (value not drawn)
SH-JP6  969102-0000-DA  [SNT-100-BK-G]  (value not drawn)
SH-JP7  969102-0000-DA  [SNT-100-BK-G]  (value not drawn)
SH-JP8  969102-0000-DA  [SNT-100-BK-G]  (value not drawn)
SH-JP9  969102-0000-DA  [SNT-100-BK-G]  (value not drawn)
SH-JP10  969102-0000-DA  [SNT-100-BK-G]  (value not drawn)
SH-JP11  969102-0000-DA  [SNT-100-BK-G]  (value not drawn)
SH-JP12  969102-0000-DA  [SNT-100-BK-G]  (value not drawn)
SH-JP13  969102-0000-DA  [SNT-100-BK-G]  (value not drawn)
SH-JP14  969102-0000-DA  [SNT-100-BK-G]  (value not drawn)
SH-JP15  969102-0000-DA  [SNT-100-BK-G]  (value not drawn)
SH-JP16  969102-0000-DA  [SNT-100-BK-G]  (value not drawn)
SH-JP17  969102-0000-DA  [SNT-100-BK-G]  (value not drawn)
SH-JP18  969102-0000-DA  [SNT-100-BK-G]  (value not drawn)
SH-JP19  969102-0000-DA  [SNT-100-BK-G]  (value not drawn)
ZZ1  This Assembly Note is for PCB labels only  [AssemblyNoteLabel]  (no BOM)
ZZ2  These assemblies are ESD sensitive, ESD precautions shall be observed.  [AssemblyNote]  (no BOM)
ZZ3  These assemblies must be clean and free from flux and all contaminants. Use of no clean flux is not acceptable.  [AssemblyNote]  (no BOM)
ZZ4  These assemblies must comply with workmanship standards IPC-A-610 Class 2, unless otherwise specified.  [AssemblyNote]  (no BOM)
ZZ5  Please place P9- Terminal; P10- Terminal; P11- Terminal; to P1; P2; P3  [AssemblyNote]  (no BOM)

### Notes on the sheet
- Variant
- 001
- Label Table
- All parts
- BQ76PL536ATPAPRQ1
- 002
- BQ76PL536ATPAPR

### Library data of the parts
!PCB1 = PCB: Manufacturer: Any; PartNumber: PWR763; SymbolCreator: a0412235
Aarvark = MechPart: Aardvark embedded systems interface; SymbolCreator: codlsc; CompType: Mechanical; U/M: EA
CAUTION_1 = IEC_HighVoltage: IEC 61010-1 High Voltage Warning; SymbolCreator: a0412235
FID1-FID3 = Fiducial: Fiducial mark.  There is nothing to buy or mount.; SymbolCreator: codlsc
H1-H4 = 9030: BRD SPT SNAP LOCK SCREW MNT 3/8"; Manufacturer: Keystone; SymbolCreator: a0412235; CompType: Nylon Spacer
LBL1 = THT-14-423-10: Thermal Transfer Printable Labels, 0.650" W x 0.200" H - 10,000 per roll; Manufacturer: Brady; SymbolCreator: a0412235; CompType: Label
Logo1 = TI_Logo: Texas Instrument Corporate Signature; SymbolCreator: codlsc
Logo2 = Pb-Free: SymbolCreator: a0412235
Logo3 = FCC_disclaimer: SymbolCreator: codlsc
P9-P11 = MechPart: Will add component to BOM.  Useful for cables, nuts, etc. not in libraries; Manufacturer: 0395000007; SymbolCreator: codlsc; CompType: Mechanical; U/M: EA; Discription: TERM BLOCK PLUG 7POS STR 3.5MM
SH-J1-SH-J8 SH-JP1-SH-JP19 = 969102-0000-DA: Shunt, 100mil, Gold plated, Black; Manufacturer: 3M; Alternate Manufacturer: Samtec; Value: 1x2; Note: You can "mate" this to a header by matching the designator.  i.e. use SH-J3 for header J3
ZZ1 = AssemblyNoteLabel: SymbolCreator: a0412235
ZZ2-ZZ5 = AssemblyNote: SymbolCreator: codlsc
